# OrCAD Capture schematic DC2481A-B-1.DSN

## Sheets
1 PAGE1: size C; title: HIGH EFFICIENCY, POLY-PHASE, DC/DC STEP-DOWN; rev: 1; company: TM
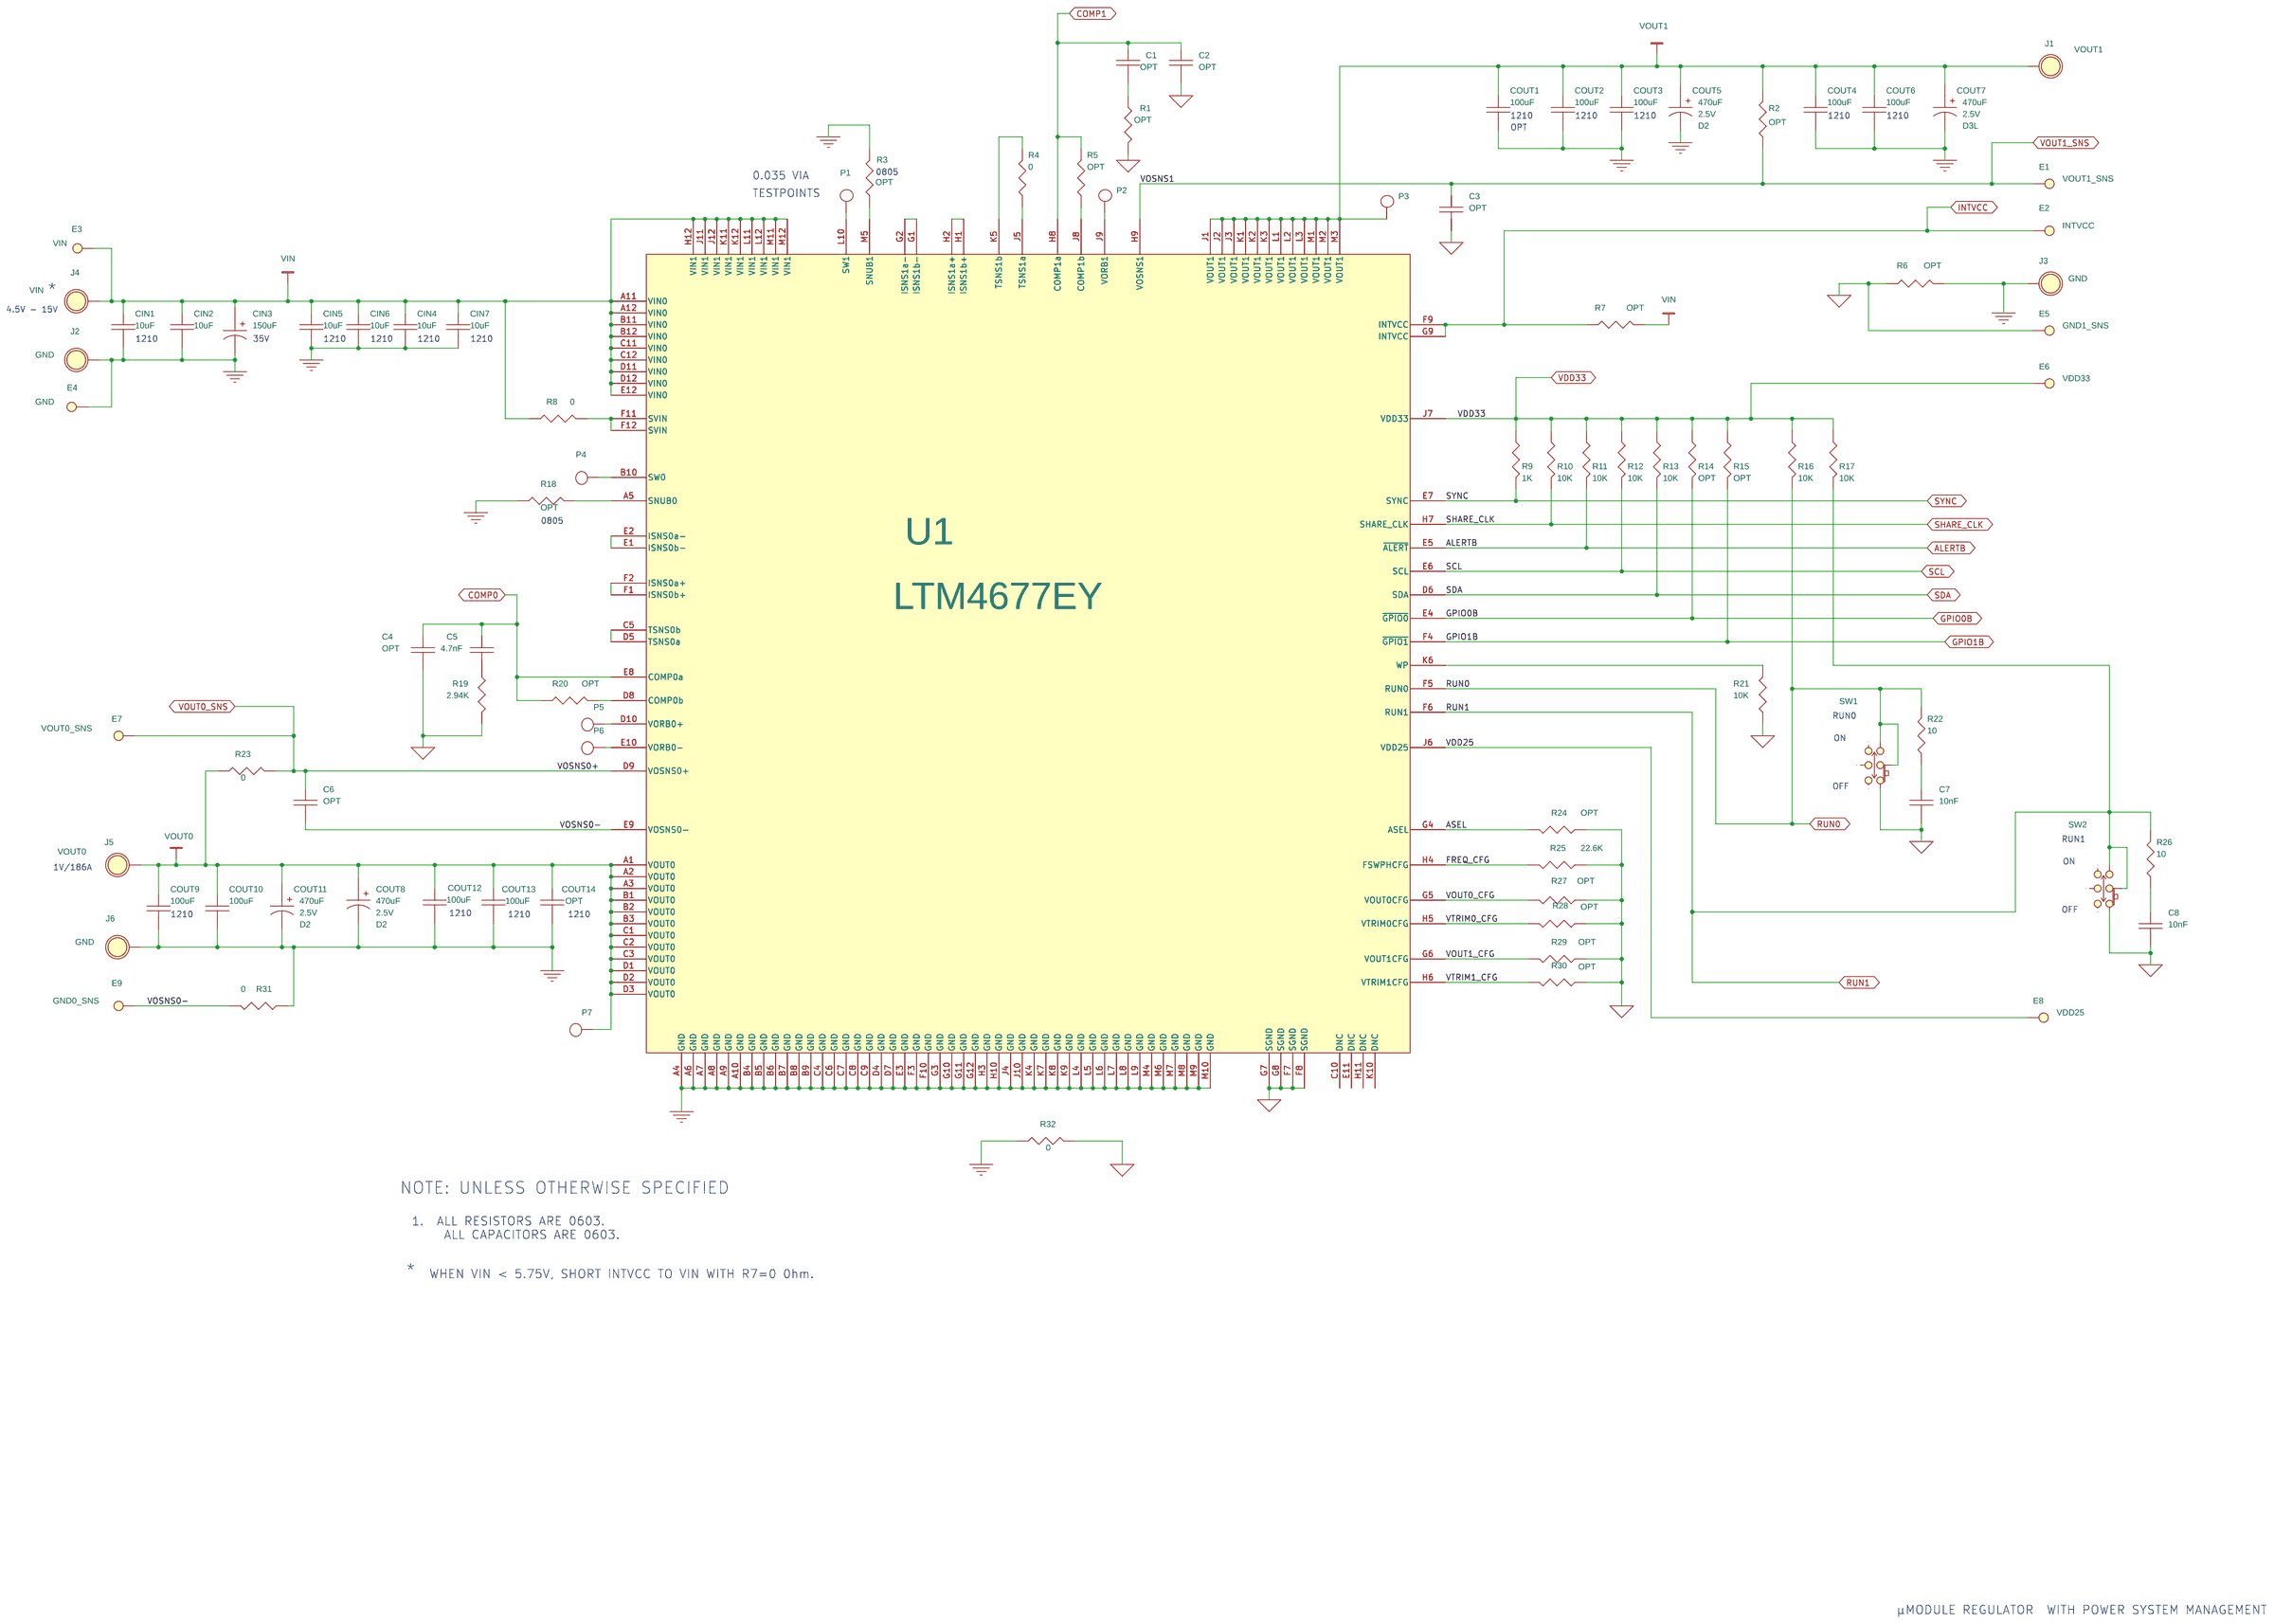
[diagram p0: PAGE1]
2 PAGE2: size Custom
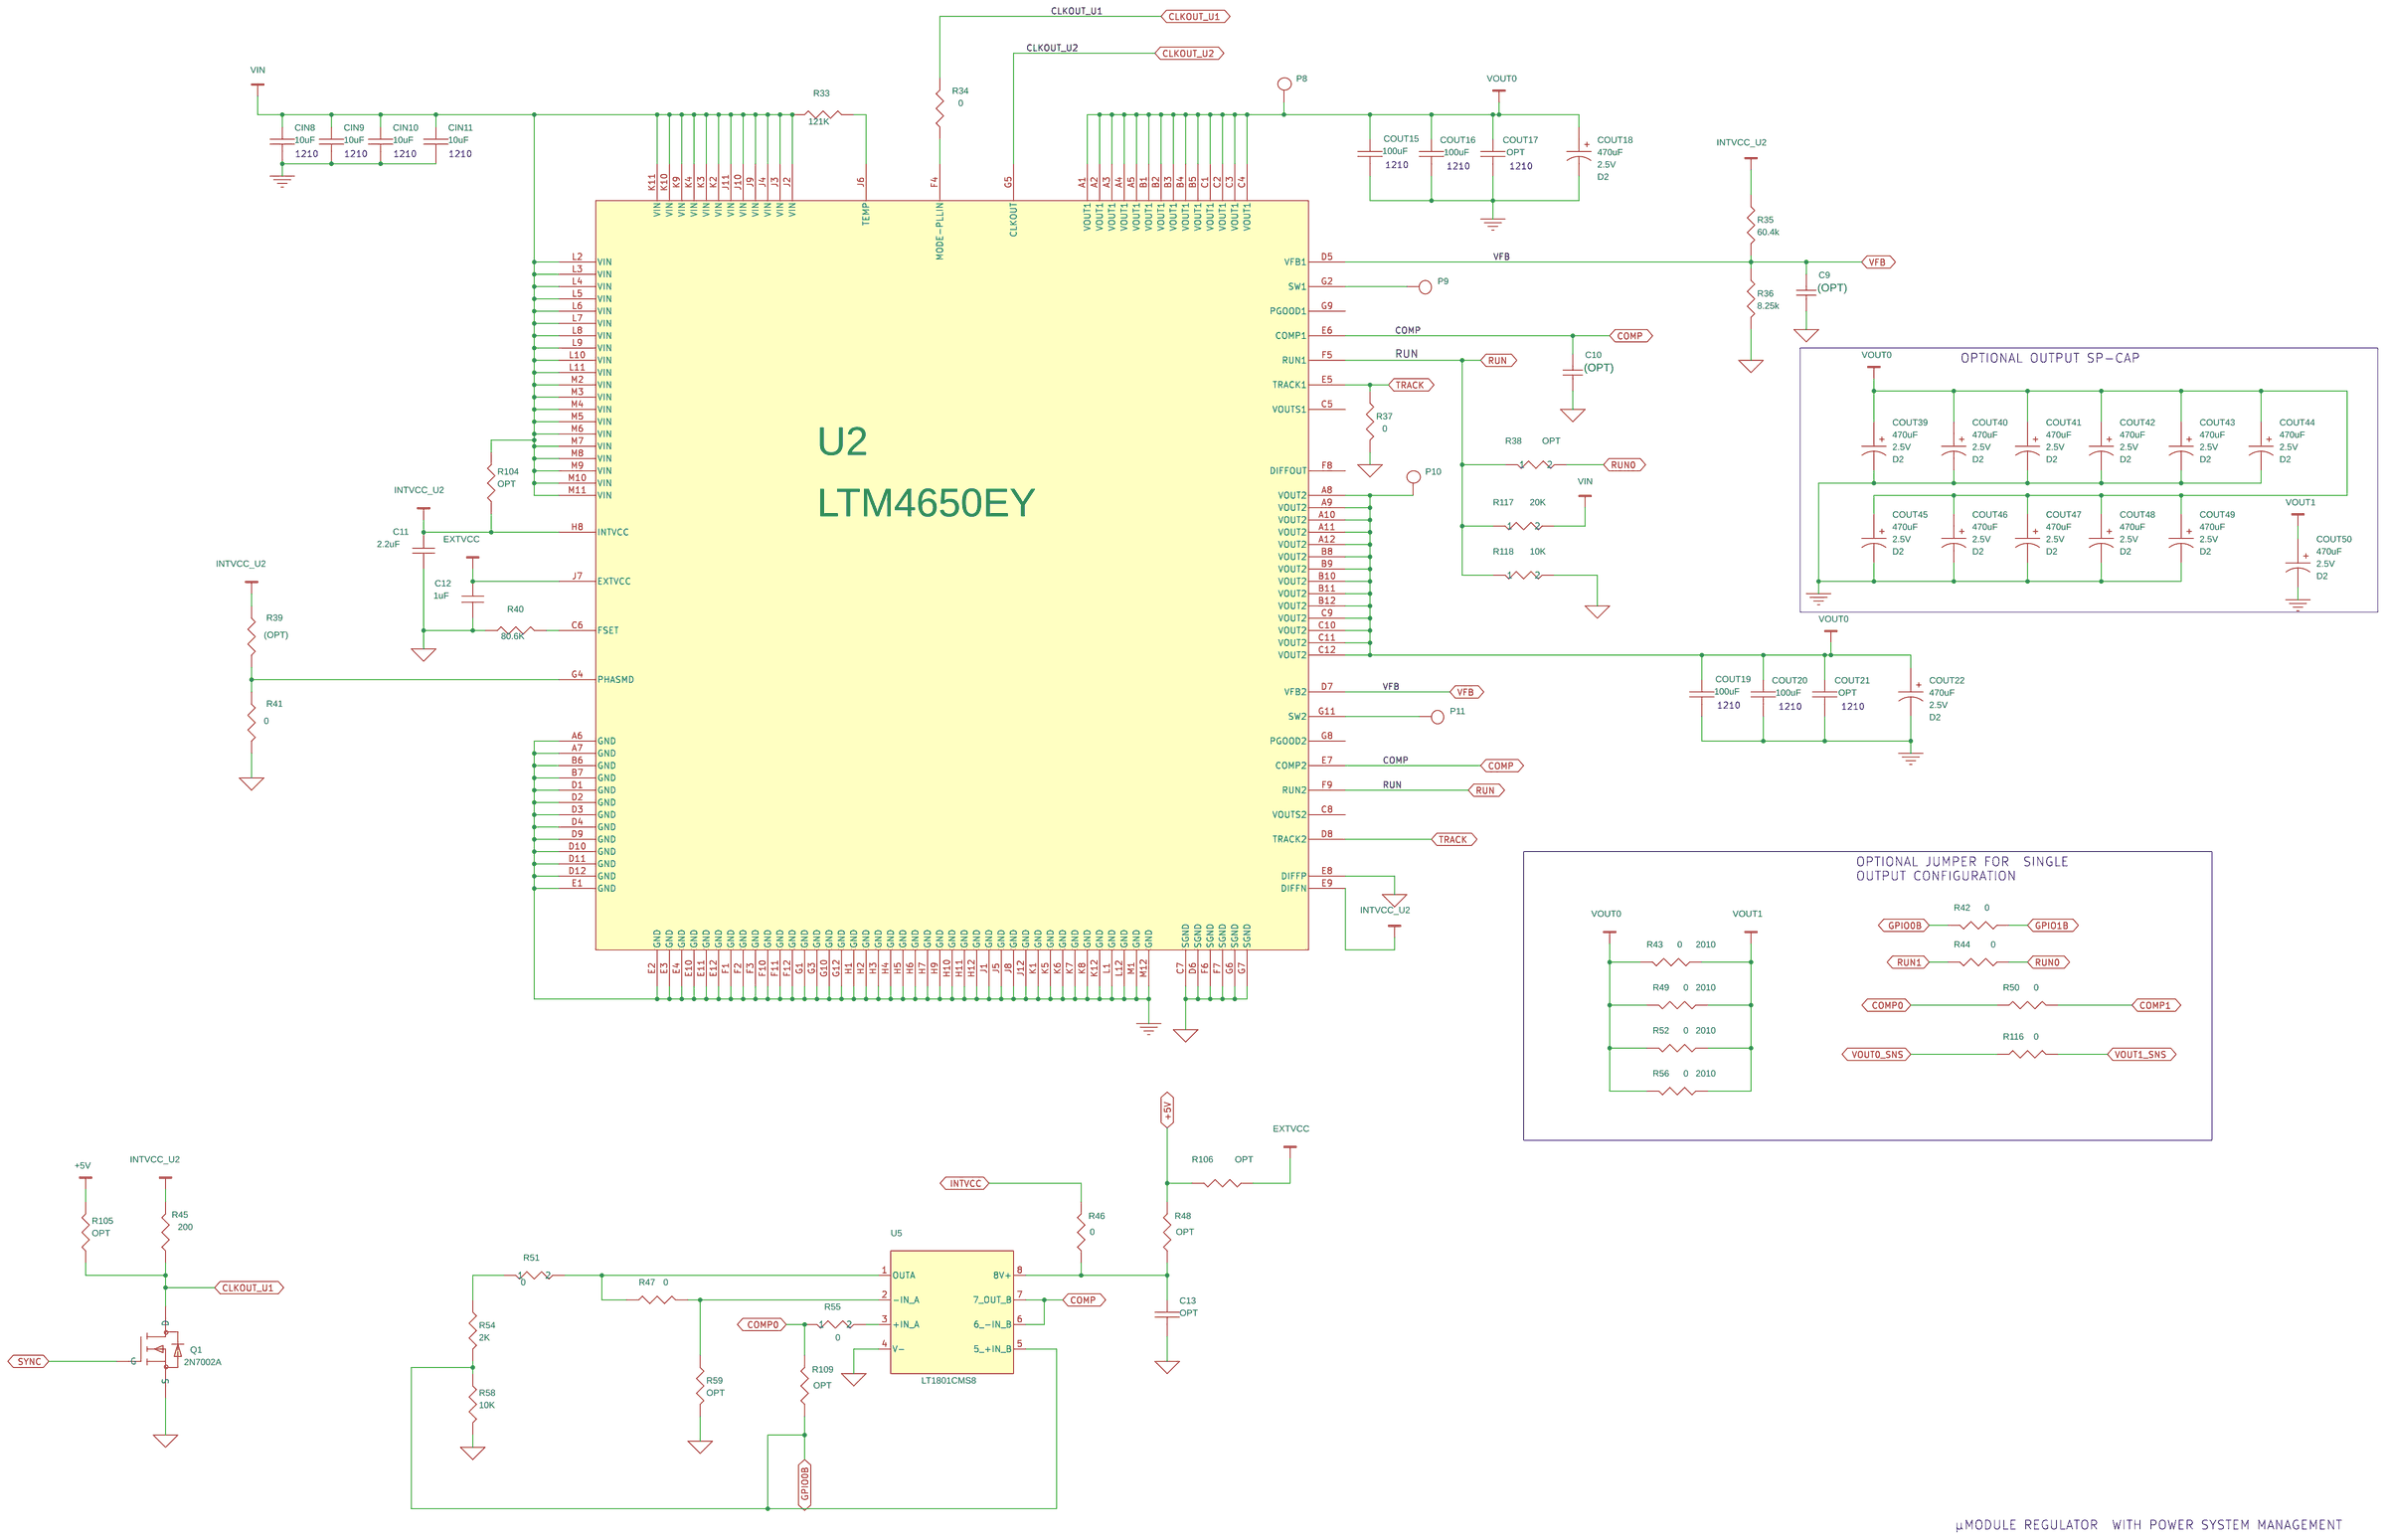
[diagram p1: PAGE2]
3 PAGE3: size Custom
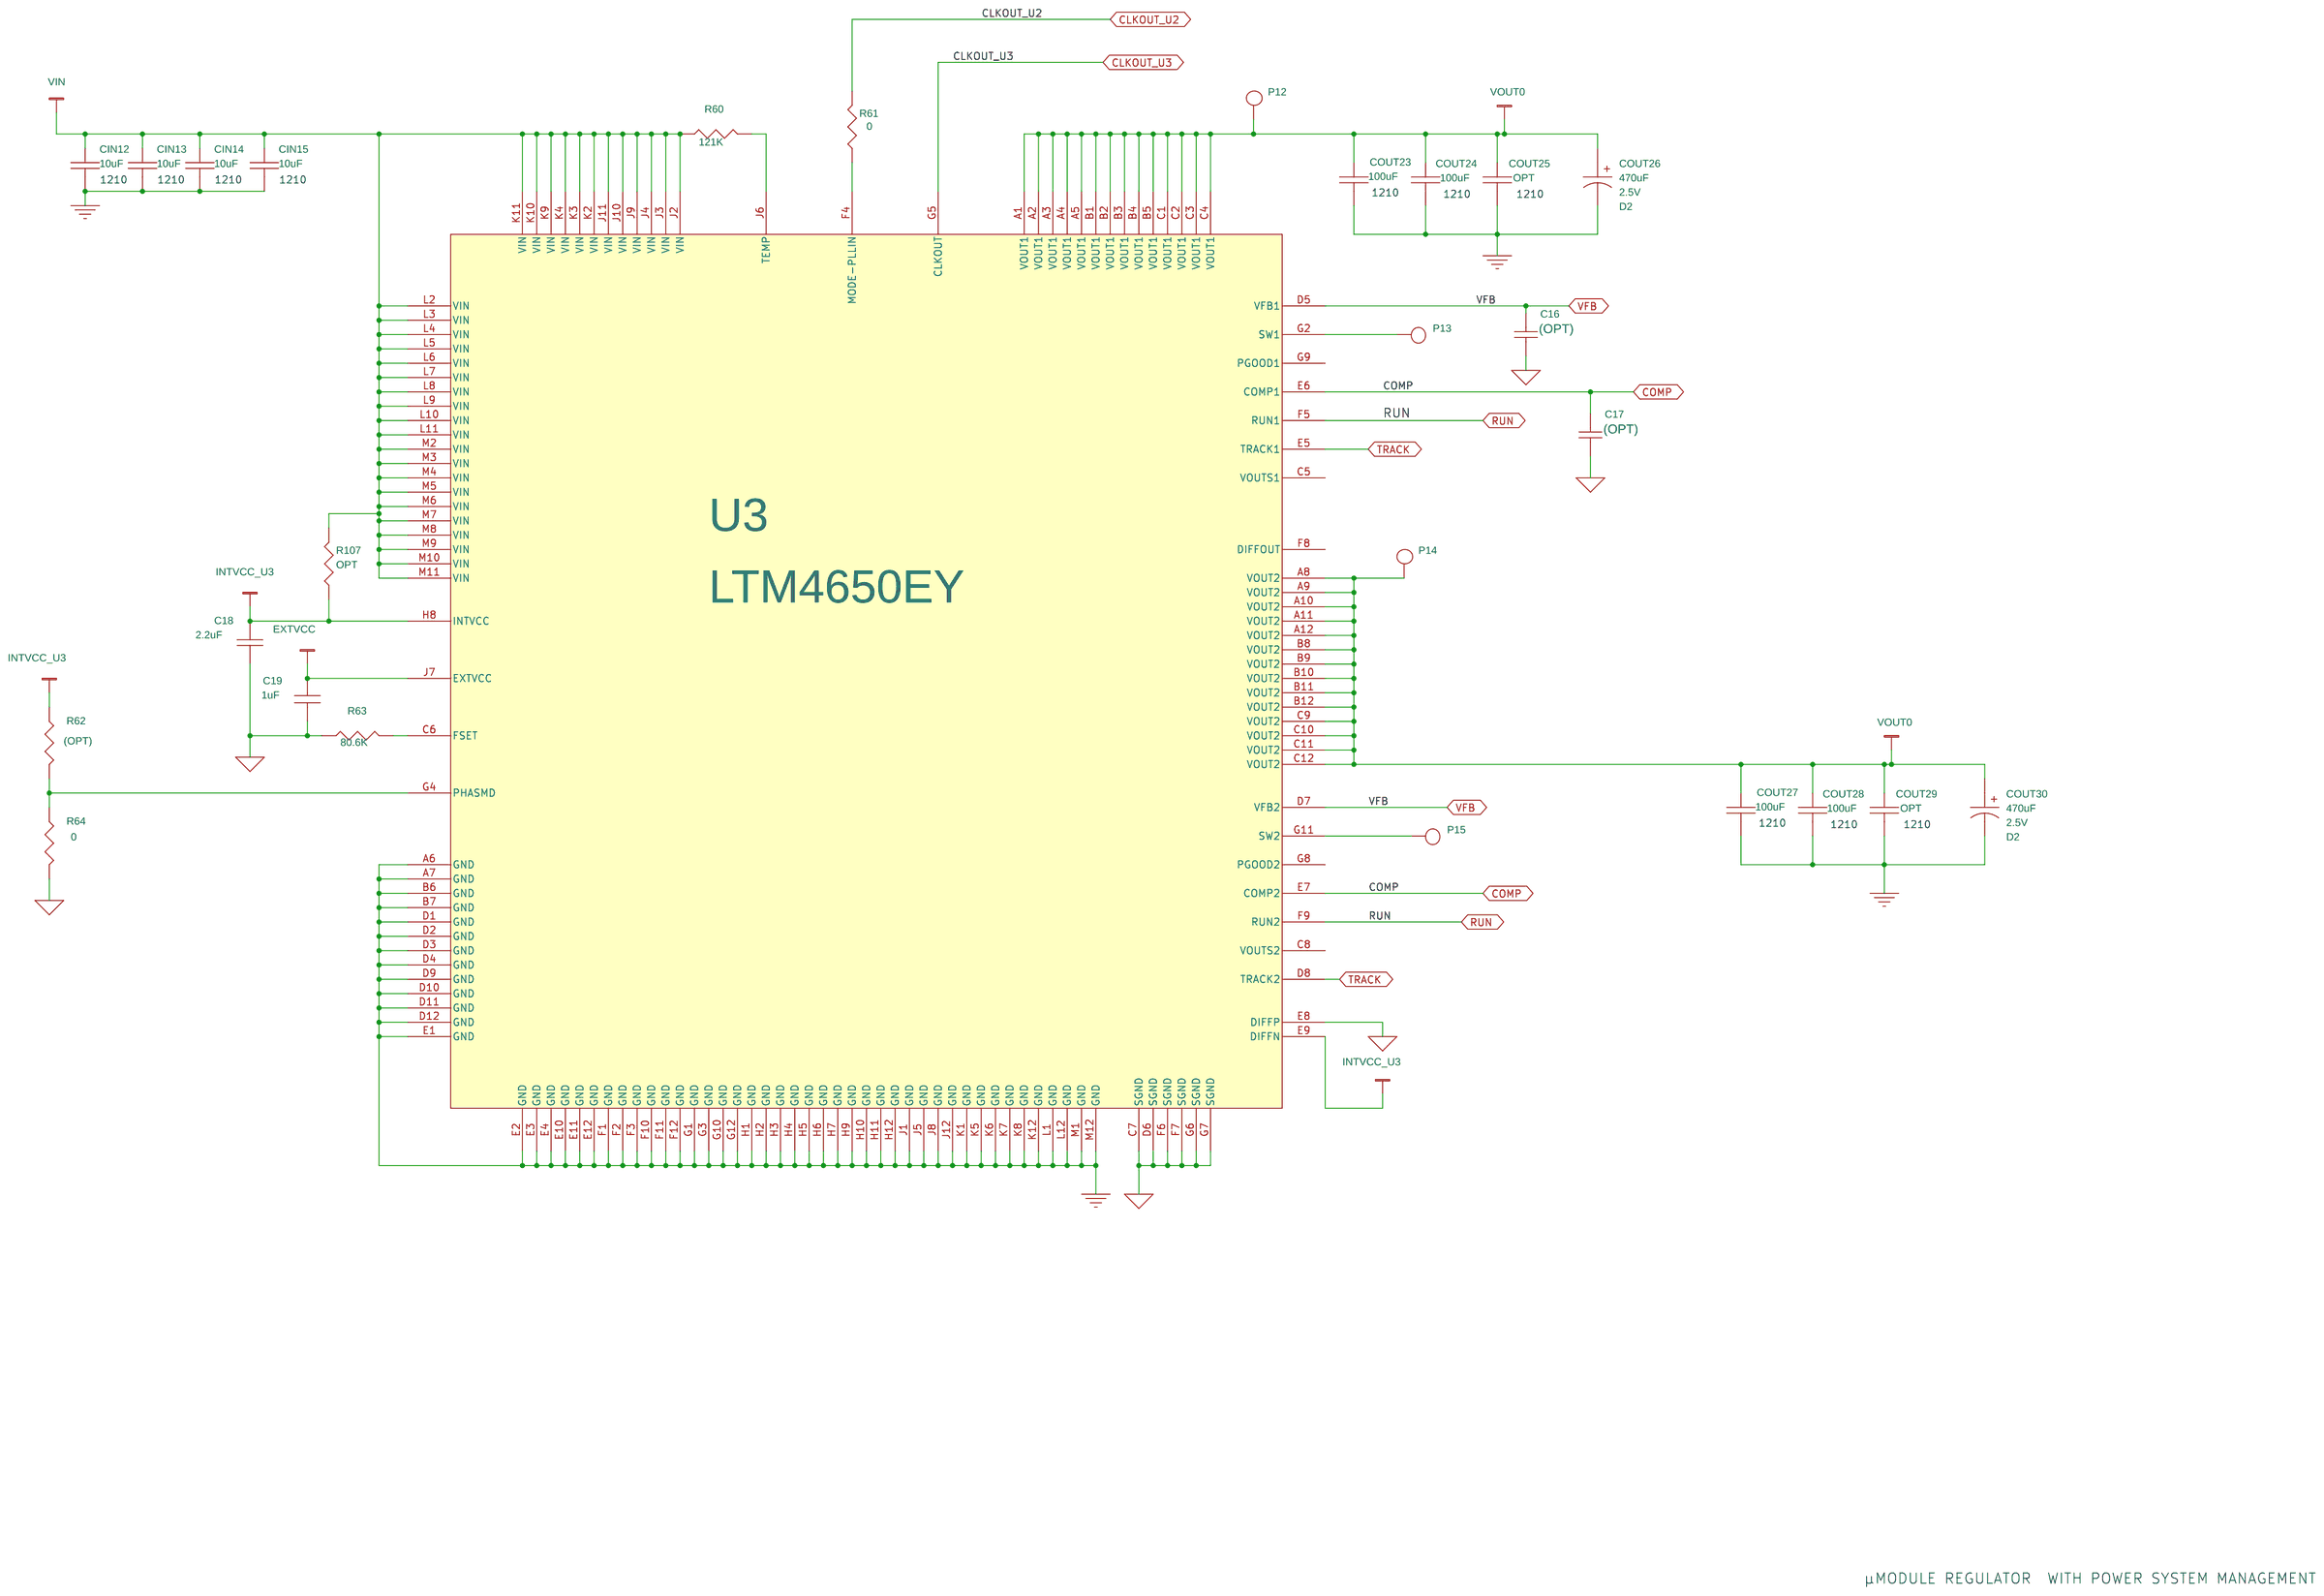
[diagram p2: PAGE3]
4 PAGE4: size Custom
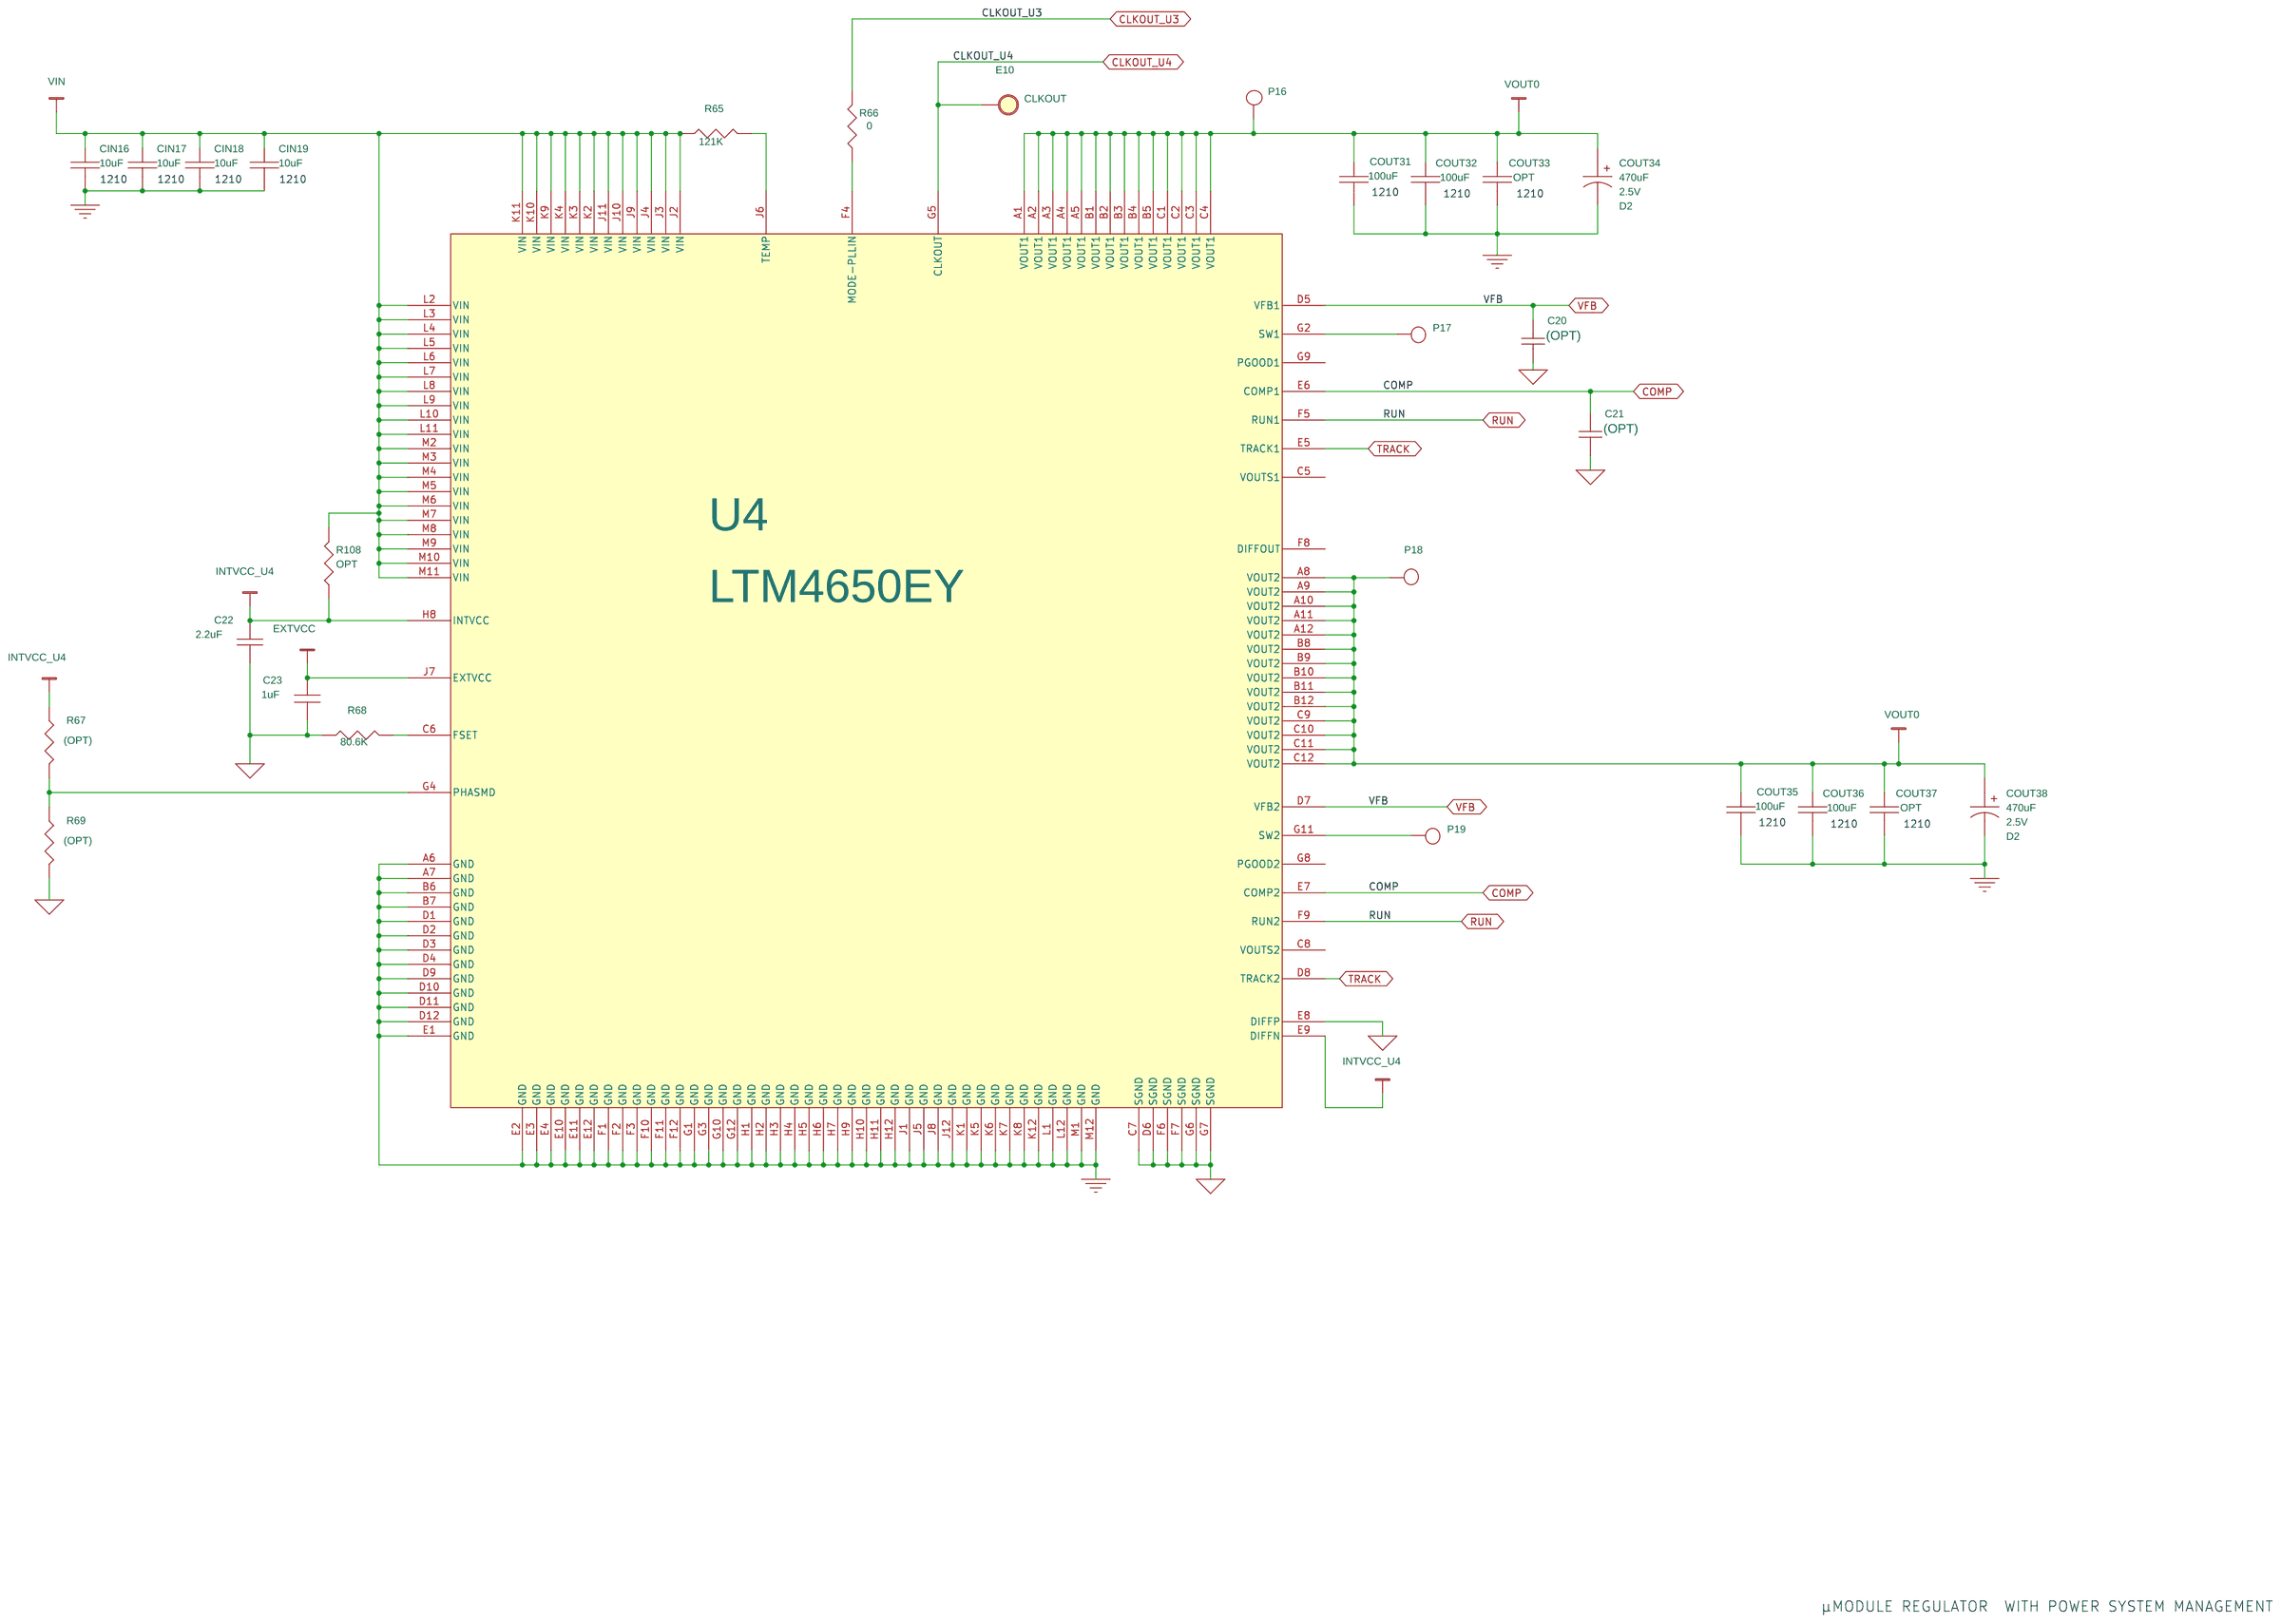
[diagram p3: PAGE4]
5 PAGE5: size Custom
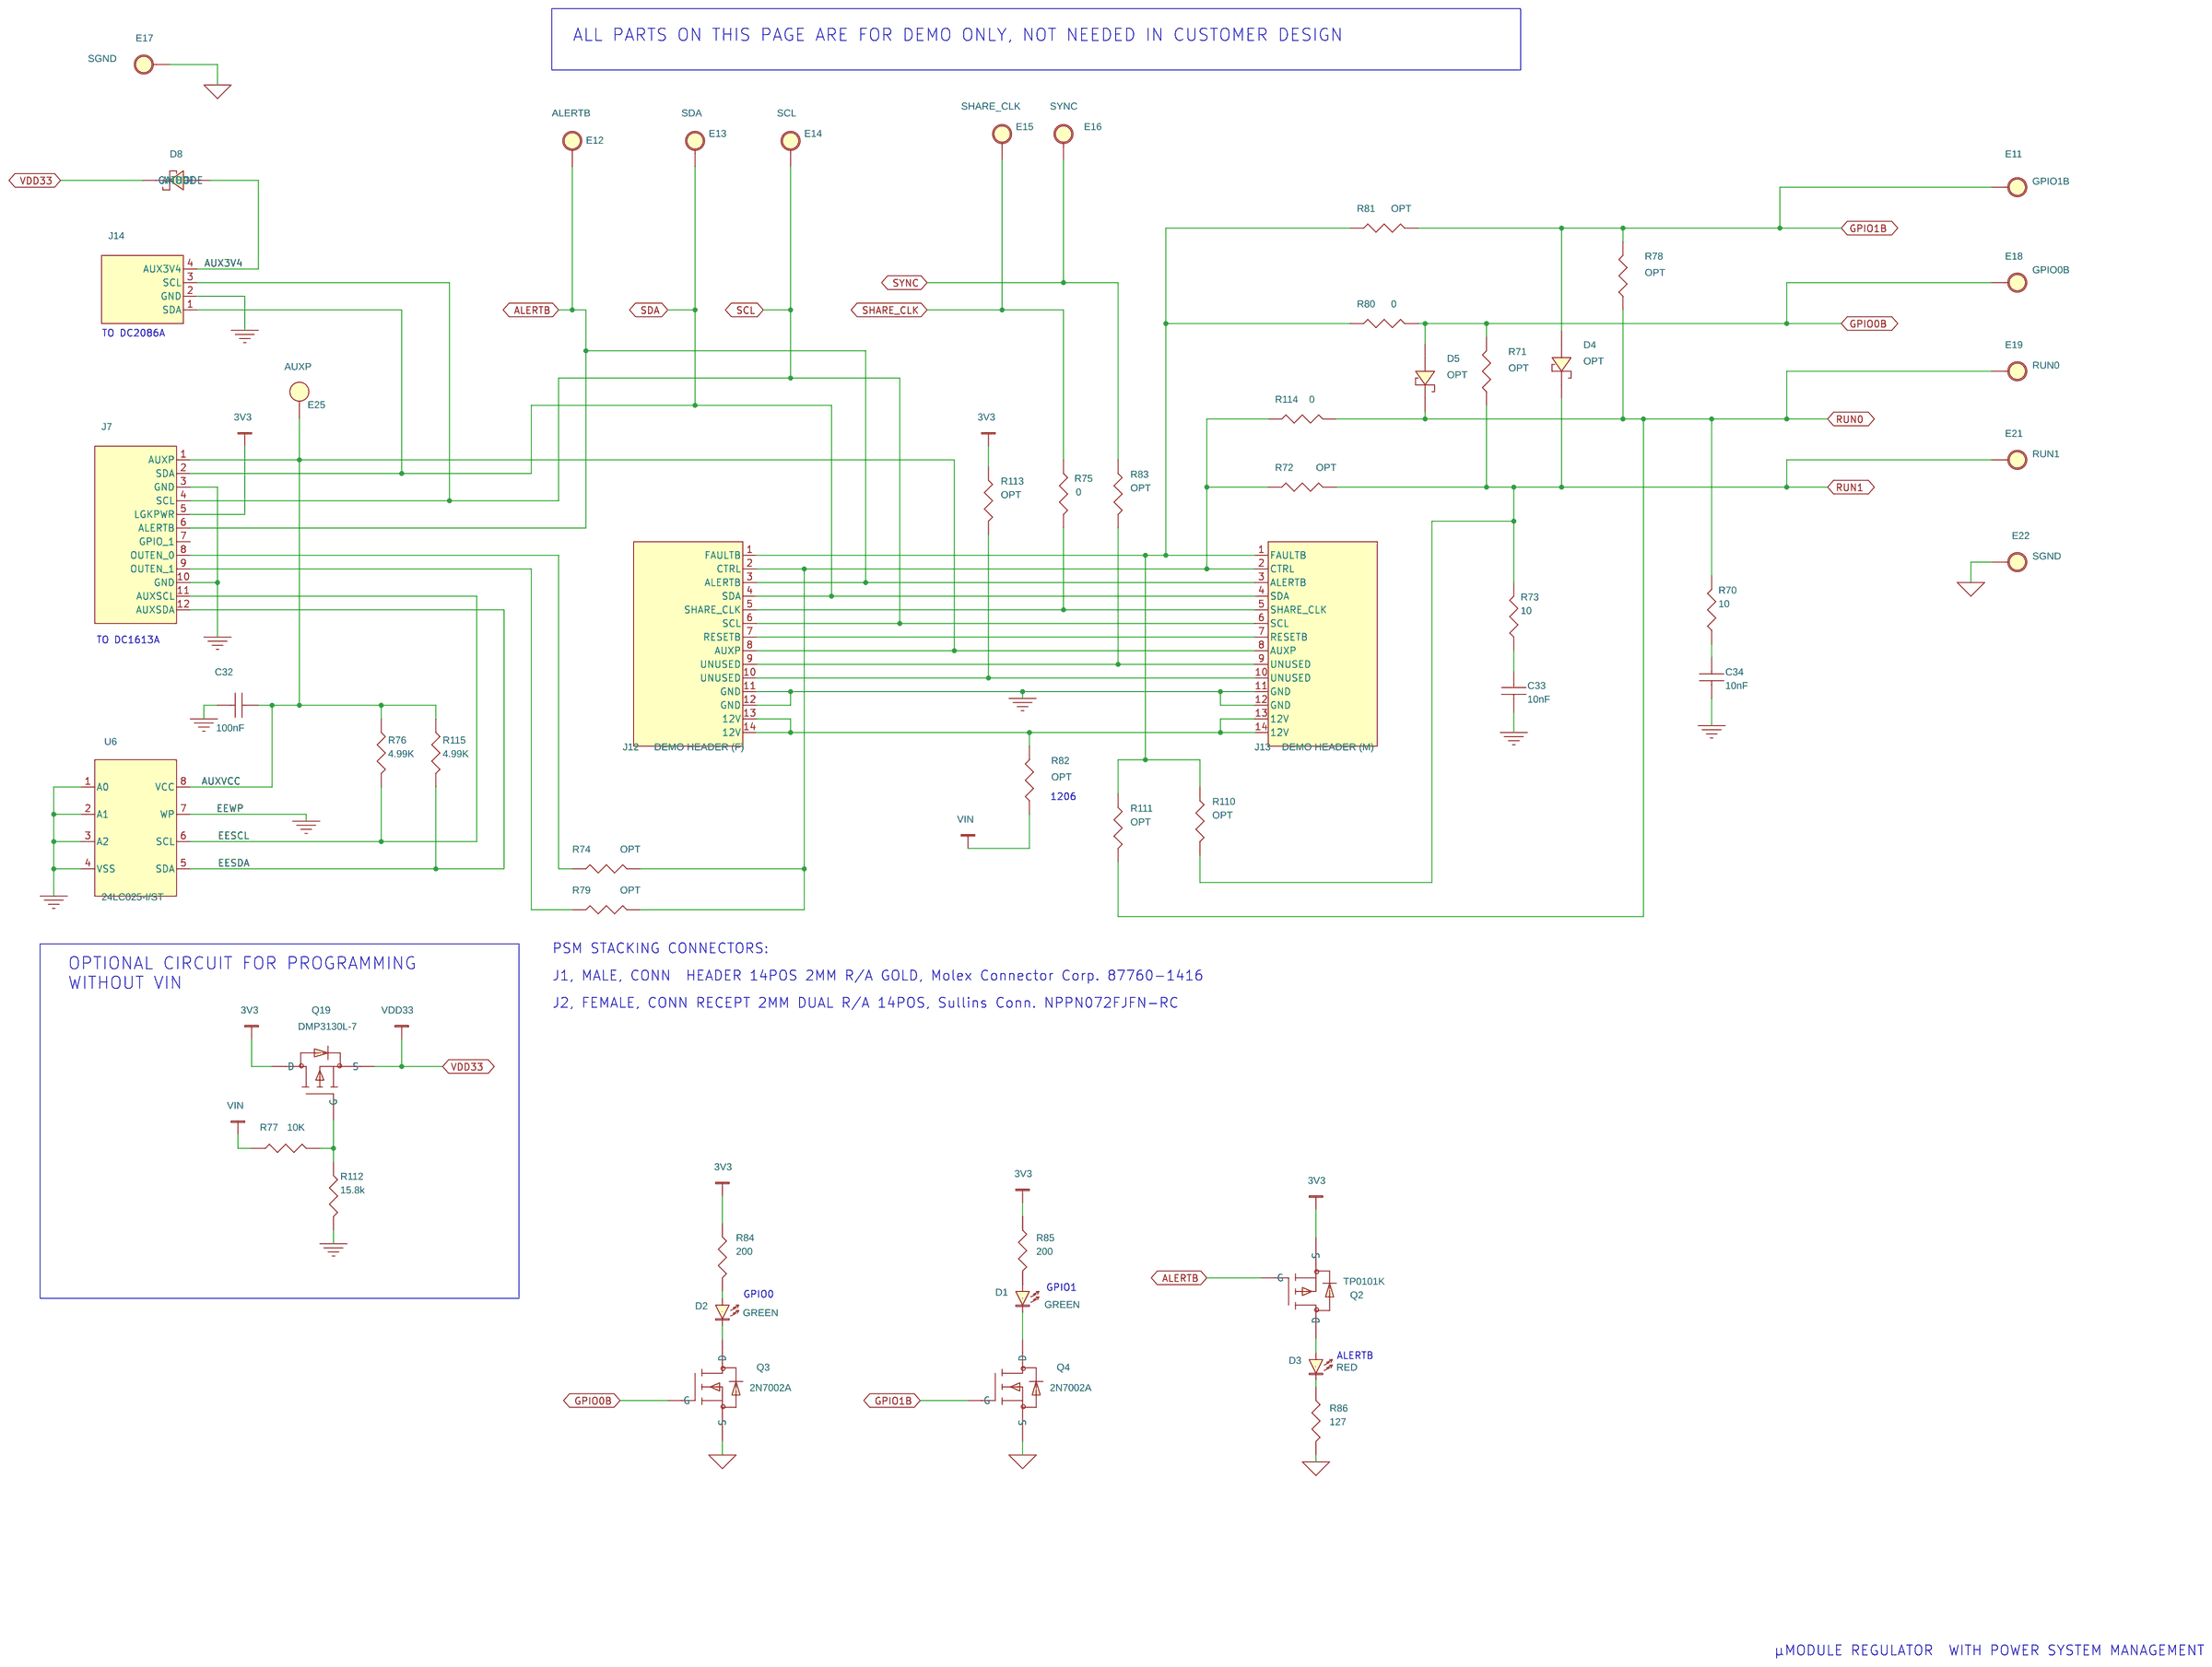
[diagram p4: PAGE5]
6 PAGE6: size B
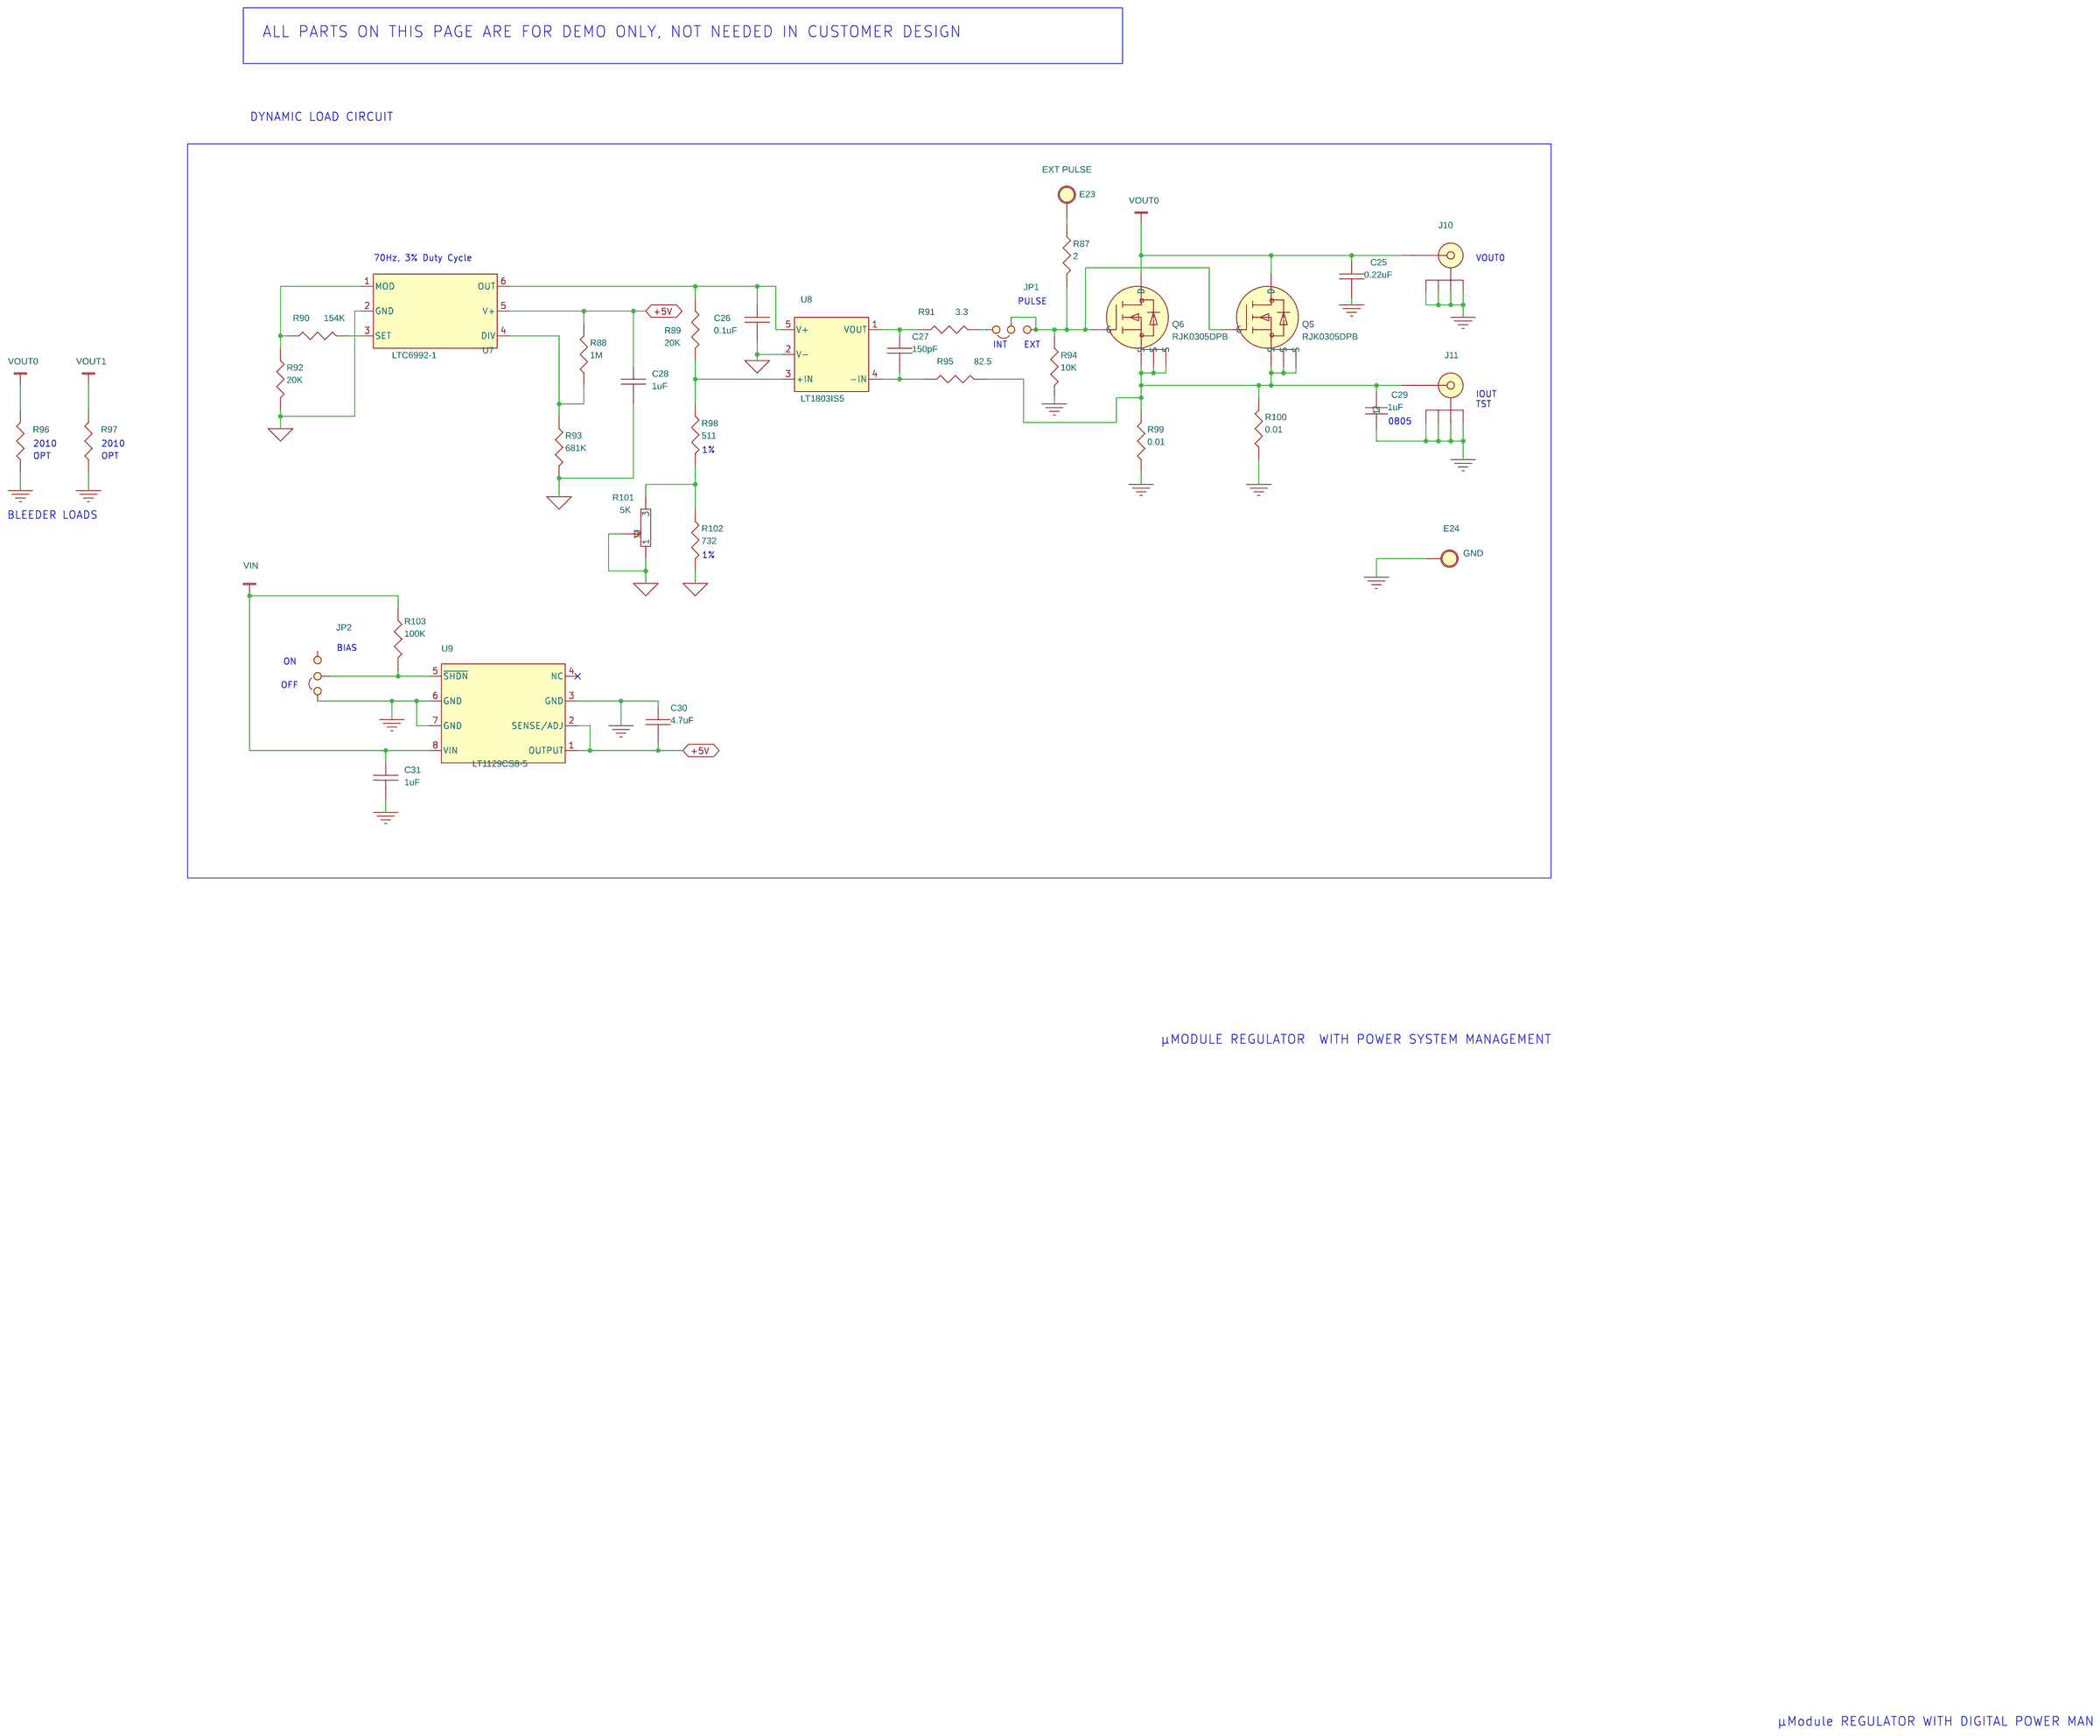
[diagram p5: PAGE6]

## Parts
sheet PAGE1
C1  OPT  [0603]
C2  OPT  [0603]
C3  OPT  [0603]
C4  OPT  [0603]
C5  4.7nF  [0603]
C6  OPT  [0603]
C7  10nF  [0603]
C8  10nF  [0603]
CIN1  10uF  [1210]
CIN2  10uF  [1210]
CIN3  150uF  [SANYO\8X10]
CIN4  10uF  [1210]
CIN5  10uF  [1210]
CIN6  10uF  [1210]
CIN7  10uF  [1210]
COUT1  100uF  [1210]
COUT2  100uF  [1210]
COUT3  100uF  [1210]
COUT4  100uF  [1210]
COUT5  470uF  [D2]
COUT6  100uF  [1210]
COUT7  470uF  [D3L]
COUT8  470uF  [D2]
COUT9  100uF  [1210]
COUT10  100uF  [1210]
COUT11  470uF  [D2]
COUT12  100uF  [1210]
COUT13  100uF  [1210]
COUT14  OPT  [1210]
E1  TURRETS  [TURRETS]
E2  INTVCC  [TURRETS]
E3  TURRETS  [TURRETS]
E4  GND  [TURRETS]
E5  TURRETS  [TURRETS]
E6  VDD33  [TURRETS]
E7  TURRETS  [TURRETS]
E8  VDD25  [TURRETS]
E9  TURRETS  [TURRETS]
J1  BANANA SMALL  [CON\LUG\10]
J2  BANANA SMALL  [CON\LUG\10]
J3  BANANA SMALL  [CON\LUG\10]
J4  BANANA SMALL  [CON\LUG\10]
J5  BANANA SMALL  [CON\LUG\10]
J6  BANANA SMALL  [CON\LUG\10]
P1  TURRETS  [PAD]
P2  TURRETS  [PAD]
P3  TURRETS  [PAD]
P4  TURRETS  [PAD]
P5  TURRETS  [PAD]
P6  TURRETS  [PAD]
P7  TURRETS  [PAD]
R1  OPT  [0603]
R2  OPT  [0603]
R3  OPT  [0805]
R4  0  [0603]
R5  OPT  [0603]
R6  OPT  [0603]
R7  OPT  [0603]
R8  0  [0603]
R9  1K  [0603]
R10  10K  [0603]
R11  10K  [0603]
R12  10K  [0603]
R13  10K  [0603]
R14  OPT  [0603]
R15  OPT  [0603]
R16  10K  [0603]
R17  10K  [0603]
R18  OPT  [0805]
R19  2.94K  [0603]
R20  OPT  [0603]
R21  10K  [0603]
R22  10  [0603]
R23  0  [0603]
R24  OPT  [0603]
R25  22.6K  [0603]
R26  10  [0603]
R27  OPT  [0603]
R28  OPT  [0603]
R29  OPT  [0603]
R30  OPT  [0603]
R31  0  [0603]
R32  0  [0603]
SW1  JP3X1/079\NO\12  [JS202011]
SW2  JP3X1/079\NO\12  [JS202011]
U1  LTM4677EY  [a]
sheet PAGE2
C9  TBD  [0603]
C10  TBD  [0603]
C11  2.2uF  [0603]
C12  1uF  [0603]
C13  OPT  [0603]
CIN8  10uF  [1210]
CIN9  10uF  [1210]
CIN10  10uF  [1210]
CIN11  10uF  [1210]
COUT15  100uF  [1210]
COUT16  100uF  [1210]
COUT17  OPT  [1210]
COUT18  470uF  [D2]
COUT19  100uF  [1210]
COUT20  100uF  [1210]
COUT21  OPT  [1210]
COUT22  470uF  [D2]
COUT39  470uF  [D2]
COUT40  470uF  [D2]
COUT41  470uF  [D2]
COUT42  470uF  [D2]
COUT43  470uF  [D2]
COUT44  470uF  [D2]
COUT45  470uF  [D2]
COUT46  470uF  [D2]
COUT47  470uF  [D2]
COUT48  470uF  [D2]
COUT49  470uF  [D2]
COUT50  470uF  [D2]
P8  TURRETS  [PAD]
P9  TURRETS  [PAD]
P10  TURRETS  [PAD]
P11  TURRETS  [PAD]
Q1  2N7002A  [SOT-23]
R33  121K  [0603]
R34  0  [0603]
R35  60.4k  [0603]
R36  8.25k  [0603]
R37  0  [0603]
R38  OPT  [0603]
R39  TBD  [0603]
R40  80.6K  [0603]
R41  TBD  [0603]
R42  0  [0603]
R43  0  [2010]
R44  0  [0603]
R45  200  [0603]
R46  0  [0603]
R47  0  [0603]
R48  OPT  [0603]
R49  0  [2010]
R50  0  [0603]
R51  0  [0603]
R52  0  [2010]
R54  2K  [0603]
R55  0  [0603]
R56  0  [2010]
R58  10K  [0603]
R59  OPT  [0603]
R104  OPT  [0603]
R105  OPT  [0603]
R106  OPT  [0603]
R109  OPT  [0603]
R116  0  [0603]
R117  20K  [0603]
R118  10K  [0603]
U2  Volt. Reg.  [LTM4620]
U5  LT1801CMS8  [MSOP-8]
sheet PAGE3
C16  TBD  [0603]
C17  TBD  [0603]
C18  2.2uF  [0603]
C19  1uF  [0603]
CIN12  10uF  [1210]
CIN13  10uF  [1210]
CIN14  10uF  [1210]
CIN15  10uF  [1210]
COUT23  100uF  [1210]
COUT24  100uF  [1210]
COUT25  OPT  [1210]
COUT26  470uF  [D2]
COUT27  100uF  [1210]
COUT28  100uF  [1210]
COUT29  OPT  [1210]
COUT30  470uF  [D2]
P12  TURRETS  [PAD]
P13  TURRETS  [PAD]
P14  TURRETS  [PAD]
P15  TURRETS  [PAD]
R60  121K  [0603]
R61  0  [0603]
R62  TBD  [0603]
R63  80.6K  [0603]
R64  TBD  [0603]
R107  OPT  [0603]
U3  Volt. Reg.  [LTM4620]
sheet PAGE4
C20  TBD  [0603]
C21  TBD  [0603]
C22  2.2uF  [0603]
C23  1uF  [0603]
CIN16  10uF  [1210]
CIN17  10uF  [1210]
CIN18  10uF  [1210]
CIN19  10uF  [1210]
COUT31  100uF  [1210]
COUT32  100uF  [1210]
COUT33  OPT  [1210]
COUT34  470uF  [D2]
COUT35  100uF  [1210]
COUT36  100uF  [1210]
COUT37  OPT  [1210]
COUT38  470uF  [D2]
E10  TURRETS  [TURRETS]
P16  TURRETS  [PAD]
P17  TURRETS  [PAD]
P18  TURRETS  [PAD]
P19  TURRETS  [PAD]
R65  121K  [0603]
R66  0  [0603]
R67  TBD  [0603]
R68  80.6K  [0603]
R69  TBD  [0603]
R108  OPT  [0603]
U4  Volt. Reg.  [LTM4620]
sheet PAGE5
C32  100nF  [0603]
C33  10nF  [0603]
C34  10nF  [0603]
D1  GREEN  [led]
D2  GREEN  [led]
D3  RED  [led]
D4  OPT  [SOD323]
D5  OPT  [SOD323]
D8  DIODE SCHOTTKY  [PMEG2005AEL]
E11  TURRETS  [TURRETS]
E12  TURRETS  [TURRETS]
E13  TURRETS  [TURRETS]
E14  TURRETS  [TURRETS]
E15  TURRETS  [TURRETS]
E16  TURRETS  [TURRETS]
E17  SGND  [TURRETS]
E18  TURRETS  [TURRETS]
E19  TURRETS  [TURRETS]
E21  TURRETS  [TURRETS]
E22  SGND  [TURRETS]
E25  AUXP  [TURRETS]
J7  HD2X6-079  [HD2X6-079-MOLEX]
J12  DEMO HEADER (F)  [NPPN072FJFN-RC]
J13  DEMO HEADER (M)  [NPPN072FJFN]
J14  HD2X6-079-PMBUS_0  [DF3A-4P-2DSA]
Q2  TP0101K  [SOT-23]
Q3  2N7002A  [SOT-23]
Q4  2N7002A  [SOT-23]
Q19  DMP3130L-7  [SOT-23]
R70  10  [0603]
R71  OPT  [0603]
R72  OPT  [0603]
R73  10  [0603]
R74  OPT  [0603]
R75  0  [0603]
R76  4.99K  [0603]
R77  10K  [0603]
R78  OPT  [0603]
R79  OPT  [0603]
R80  0  [0603]
R81  OPT  [0603]
R82  OPT  [1206]
R83  OPT  [0603]
R84  200  [0603]
R85  200  [0603]
R86  127  [0603]
R110  OPT  [0603]
R111  OPT  [0603]
R112  15.8k  [0603]
R113  OPT  [0603]
R114  0  [0603]
R115  4.99K  [0603]
U6  24LC025-I/ST  [TSSOP-8_4.4MM]
sheet PAGE6
C25  0.22uF  [0805]
C26  0.1uF  [1206]
C27  150pF  [0603]
C28  1uF  [1206]
C29  1uF  [0805]
C30  4.7uF  [0603]
C31  1uF  [1206]
E23  TURRETS  [TURRETS]
E24  TURRETS  [TURRETS]
J10  XXX  [BNC]
J11  XXX  [BNC]
JP1  JP3X1/079\NO\12  [HD1X3-079]
JP2  JP3X1/079\NO\12  [HD1X3-079]
Q5  RJK0305DPB  [LFPAK]
Q6  RJK0305DPB  [LFPAK]
R87  2  [0603]
R88  1M  [0603]
R89  20K  [0603]
R90  154K  [0603]
R91  3.3  [0603]
R92  20K  [0603]
R93  681K  [0603]
R94  10K  [0603]
R95  82.5  [0603]
R96  OPT  [2512SENSE]
R97  OPT  [2512SENSE]
R98  511  [0603]
R99  0.01  [2010]
R100  0.01  [2010]
R101  5K  [POTENTIOMETER/3386]
R102  732  [0603]
R103  100K  [0603]
U7  LTC6992-1  [S6-TSOT23]
U8  LT1803IS5  [S5-TSOT23]
U9  LT1129CS8-5  [SO8NB]

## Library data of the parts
C1-C6 = CAP0603_1: Component: cap; Manufacturer: TDK; Manufacturer P/N: C1608C0G1H102J; Tolerance: 5%; Type: cer 0603; Vendor: Digikey; Vendor P/N: 445-1293-1-ND; Volts/Amps/Watts: 50V
C7 C8 C27 = CAP0603_2: Component: cap; Manufacturer: TDK; Manufacturer P/N: C1608C0G1H102J; Tolerance: 5%; Type: cer 0603; Vendor: Digikey
CIN1 CIN2 CIN4-CIN19 = CAP1210_1: Component: cap; Manufacturer: Taiyo Yuden; Manufacturer P/N: GMK325BJ106KN-T; Tolerance: 10%; Type: cer 1210; Vendor: Digikey; Vendor P/N: 587-1439-1-ND; Volts/Amps/Watts: 35V
CIN3 = CAPR12X5_0: Component: cap; Manufacturer: SANYO; Tolerance: 20%; Type: OS-CON; Volts/Amps/Watts: 16V
COUT1 = CAP0603_1: Component: cap; Manufacturer: TDK; Manufacturer P/N: C3225X5R0J107M; Tolerance: 20%; Type: cer 1210 X5R; Vendor: Digikey; Vendor P/N: 445-1437-1-ND; Volts/Amps/Watts: 6.3v
COUT2-COUT4 COUT6 COUT9 COUT10 COUT12-COUT17 COUT19-COUT21 COUT23-COUT25 COUT27-COUT29 COUT31-COUT33 COUT35-COUT37 = CAP0603_1: Component: cap; Manufacturer: TDK; Manufacturer P/N: C3225X5R0J107M; Part Type: CAP1210; Tolerance: 20%; Type: cer 1210 X5R; Vendor: Digikey; Vendor P/N: 445-1437-1-ND; Volts/Amps/Watts: 6.3v
COUT5 COUT7 COUT8 COUT11 COUT18 COUT22 COUT26 COUT30 COUT34 COUT38-COUT50 = CAPR12X5_0: Component: cap; Manufacturer: PANASONIC; Manufacturer P/N: EEFGX0E471R; Tolerance: 10%; Type: SP; Volts/Amps/Watts: 2.5V
E1 = TURRETS_1: Component: tp; Label: VOUT1_SNS; Vendor: Digikey; Vendor P/N: 1593-2K-ND
E2 E6 E8 = TURRETS_1: Component: tp; Label: GND; Manufacturer: Keystone; Manufacturer P/N: 1593-2; Vendor: Digikey; Vendor P/N: 1593-2K-ND
E3 = TURRETS_1: Component: tp; Label: VIN; Manufacturer: Keystone; Manufacturer P/N: 1593-2; Vendor: Digikey; Vendor P/N: 1593-2K-ND
E4 = TURRETS_1: Component: tp; Manufacturer: Keystone; Manufacturer P/N: 1593-2; Vendor: Digikey; Vendor P/N: 1593-2K-ND
E5 = TURRETS_1: Component: tp; Label: GND1_SNS; Vendor: Digikey; Vendor P/N: 1593-2K-ND
E7 = TURRETS_1: Component: tp; Label: VOUT0_SNS; Vendor: Digikey; Vendor P/N: 1593-2K-ND
E9 = TURRETS_1: Component: tp; Label: GND0_SNS; Vendor: Digikey; Vendor P/N: 1593-2K-ND
J1 = BANANA_SMALL_0: Component: conn; Label: VOUT1
J2 J3 J6 = BANANA_SMALL_0: Component: conn; Label: GND
J4 = BANANA_SMALL_0: Component: conn; Label: VIN
J5 = BANANA_SMALL_0: Component: conn; Label: VOUT0
P1-P19 = PAD_2: Component: tp; Label: <Label>; Vendor: Digikey; Vendor P/N: 1593-2K-ND
R1 R19 R35-R37 R45-R48 R54 R58 R59 R109 = RES0603_9: Component: res; Label: <label>; Manufacturer: Panasonic; Manufacturer P/N: ERJ-3EKF5901V; Tolerance: 1%; Vendor: Digikey; Vendor P/N: P5.90KHCT-ND; Volts/Amps/Watts: 0.1W
R2 = RES0603_9: Label: 0; Manufacturer: Rohm; Manufacturer P/N: RHM0.0GCT-ND; Tolerance: 5%; Vendor: Digikey; Vendor P/N: RHM0.0GCT-ND; Volts/Amps/Watts: 0.1W
R3 R18 = RES0603_9
R4 R5 R20 = RES0603_9: Manufacturer: Rohm; Manufacturer P/N: RHM0.0GCT-ND; Tolerance: 5%; Vendor: Digikey; Vendor P/N: RHM0.0GCT-ND; Volts/Amps/Watts: 0.1W
R6 R8 R32 R50 R116 = RES0603_3
R7 = RES0603_9: Label: OPT 0; Manufacturer: Rohm; Manufacturer P/N: RHM0.0GCT-ND; Vendor: Digikey
R9-R17 R21 R28 R29 = RES0603_9: Manufacturer: ROHM; Manufacturer P/N: MCR03EZPFX1002; Vendor: Digikey; Vendor P/N: RHM10.0KHCT-ND; Volts/Amps/Watts: 0.1W
R22 R26 = RES0603_1: Manufacturer: Rohm; Manufacturer P/N: RHM0.0GCT-ND; Tolerance: 5%; Vendor: Digikey; Vendor P/N: RHM0.0GCT-ND; Volts/Amps/Watts: 0.1W
R23 = RES0603_9: Manufacturer: Rohm; Manufacturer P/N: MCR03EZPFX1000; Vendor: Digikey; Vendor P/N: RHM100HCT-ND; Volts/Amps/Watts: 0.1W
R24 R25 = RES0603_9: Manufacturer: Panasonic; Manufacturer P/N: ERJ-3EKF2002V; Vendor: Digikey; Vendor P/N: P20.0KHCT-ND; Volts/Amps/Watts: 0.1W
R27 = RES0603_9: Manufacturer: Panasonic; Manufacturer P/N: ERJ-3EKF1000V; Vendor: Digikey; Vendor P/N: P100HCT-ND; Volts/Amps/Watts: 0.1W
R30 = RES0603_9: Manufacturer: Panasonic; Manufacturer P/N: ERJ-3EKF1021V; Vendor: Digikey; Vendor P/N: P1.02KHCT-ND; Volts/Amps/Watts: 0.1W
R31 = RES0603_9: Manufacturer: Yageo; Manufacturer P/N: RC0603JR-070RL; Tolerance: 5%; Vendor: Digikey; Vendor P/N: 311-0.0GRCT-ND; Volts/Amps/Watts: 0.1W
SW1 SW2 = JP3X1_079_NO_12_3
U1 = LTC3880-M0001_20: Component: IC; Manufacturer: LTC; Manufacturer P/N: LTC3880_M0001; Vendor: LTC; Vendor P/N: LTC3880_M0001
C9 C10 C16 C17 C20 C21 = CAP0603: 6th Part Field: (OPT)
C11 C18 C22 = LMK107BJ225MA
C12 C19 C23 = LMK107BJ105KA
C13 = CAP_3: Manufacturer: Taiyo Yuden; Manufacturer P/N: EMK107B7105KA-T; Type: cer 0603 X7R; Vendor: Digikey; Vendor P/N: 587-1241-1-ND; Volts/Amps/Watts: 16V
Q1 Q3 = TRANSISTOR_0: XSTR, N-CHANNEL DMOS FET
R33 R40 R60 R63 R65 R68 R104-R108 = CRCW0603121KFKEA
R34 R61 R66 = CRCW06030000Z0EA
R38 = R_2: RES, 0603 OPTION; Part Number: OPTION
R39 R62 R67 R69 = RES0603: 6th Part Field: (OPT)
R41 R64 = RES0603: 6th Part Field: 0
R42-R44 R49 R52 R56 R84-R86 = RES0603_9: Label: OPT 0; Manufacturer: Rohm; Manufacturer P/N: RHM0.0GCT-ND; Tolerance: 5%; Vendor: Digikey; Vendor P/N: RHM0.0GCT-ND; Volts/Amps/Watts: 0.1W
R51 = R: RES, 0603 OPTION; Part Number: OPTION
R55 = R_4: RES, 0603 OPTION; Part Number: OPTION
R117 = R_3: RES, 0603 OPTION; Part Number: OPTION
R118 = R_1: RES, 0603 OPTION; Part Number: OPTION
U2-U4 = LTM4620EV_0: 5th Part Field: LTM4650EY
U5 = LTC6244HMS8
E10 = TURRETS_2: Component: tp; Label: CLKOUT; Manufacturer: Keystone; Manufacturer P/N: 1593-2; Vendor: Digikey; Vendor P/N: 1593-2K-ND
C32 = CAP_NP: CAP, 0603 100nF 20% 16V X7R; Part Number: AVX 0603YC104MAT2A
C33 C34 = CAP_NP: CAP, 0603 10nF 10% 25V X7R; Part Number: AVX 06033C103KAT2A
D1 D2 = DIODE-LED_3: Manufacturer: PANASONIC; Manufacturer P/N: LN1371SGTRP
D3 = DIODE-LED_3: Label: GREEN; Manufacturer: PANASONIC
D4 D5 = DIODE_SCHOTTKY_9: DIODE, SCHOTTKY 30V, 100mA; Part Number: CENTRAL SEMI CMDSH-3-TR
D8 = DIODE_SCHOTTKY_0
E11 = TURRETS_2: Component: tp; Label: GPIO1B; Manufacturer: Keystone; Manufacturer P/N: 1593-2; Vendor: Digikey; Vendor P/N: 1593-2K-ND
E12 = TURRETS_2: Component: tp; Label: ALERTB; Manufacturer: Keystone; Manufacturer P/N: 1593-2; Vendor: Digikey; Vendor P/N: 1593-2K-ND
E13 = TURRETS_2: Component: tp; Label: SDA; Manufacturer: Keystone; Manufacturer P/N: 1593-2; Vendor: Digikey; Vendor P/N: 1593-2K-ND
E14 = TURRETS_2: Component: tp; Label: SCL; Manufacturer: Keystone; Manufacturer P/N: 1593-2; Vendor: Digikey; Vendor P/N: 1593-2K-ND
E15 = TURRETS_2: Component: tp; Label: SHARE_CLK; Manufacturer: Keystone; Manufacturer P/N: 1593-2; Vendor: Digikey; Vendor P/N: 1593-2K-ND
E16 = TURRETS_2: Component: tp; Label: SYNC; Manufacturer: Keystone; Manufacturer P/N: 1593-2; Vendor: Digikey; Vendor P/N: 1593-2K-ND
E17 E22 = TURRETS_2: Component: tp; Label: GND; Manufacturer: Keystone; Manufacturer P/N: 1593-2; Vendor: Digikey; Vendor P/N: 1593-2K-ND
E18 = TURRETS_2: Component: tp; Label: GPIO0B; Manufacturer: Keystone; Manufacturer P/N: 1593-2; Vendor: Digikey; Vendor P/N: 1593-2K-ND
E19 = TURRETS_2: Component: tp; Label: RUN0; Manufacturer: Keystone; Manufacturer P/N: 1593-2; Vendor: Digikey; Vendor P/N: 1593-2K-ND
E21 = TURRETS_2: Component: tp; Label: RUN1; Manufacturer: Keystone; Manufacturer P/N: 1593-2; Vendor: Digikey; Vendor P/N: 1593-2K-ND
E25 = E_0: TURRET; Part Number: MILL MAX 2501-2-00-80-00-00-07-0
J7 = HD2X6-079-PMBUS_2: HEADER, 12PIN 2mm STR DL; Label: DC1427A HEADER; Manufacturer: MOLEX; Manufacturer P/N: 87831-1220; Part Number: FCI 98414-G06-12ULF; Type: header 12POS 2MM VERT; Vendor: Digikey; Vendor P/N: WM18561-ND
J12 = PMBUS_HEADER20_3: HEADER, 20PIN DUAL ROW R/A; Component: con; Manufacturer: Mill Max; Manufacturer P/N: 802-40-020-20-0001; Part Number: MILL MAX 802-40-020-20-0001; Type: header RA 20 dual row; Vendor: LTC; Vendor P/N: 802-40-020-20-001
J13 = PMBUS_CONNECTOR20_3: CONN, SOCKET 20PIN  DUAL ROW R/A; Component: con; Manufacturer: Mill Max; Manufacturer P/N: 803-93-020-20-001; Part Number: MILL MAX 803-93-020-20-001; Type: conn  RA 20 dual row; Vendor: LTC; Vendor P/N: 803-93-020-20-001
J14 = HD2X6-079-PMBUS_4: HEADER, 4PIN 2mm STR DL; Manufacturer: Hirose; Type: header 4POS 2MM VERT
Q2 = P-MOSFET: XSTR, N-CHANNEL DMOS FET
Q4 = TRANSISTOR_1: XSTR, N-CHANNEL DMOS FET
Q19 = P-MOSFET: XSTR, N-CHANNEL DMOS FET; Part Number: VISHAY TP0101K-T1-E3
R70 R73 = RES0603_1: RES, 0603 10 OHMS 5% 1/10W; Manufacturer: Rohm; Manufacturer P/N: RHM0.0GCT-ND; Part Number: VISHAY CRCW060310R0JNEA; Tolerance: 5%; Vendor: Digikey; Vendor P/N: RHM0.0GCT-ND; Volts/Amps/Watts: 0.1W
R71 R78 R79 R83 R110 R111 R113 = RES0603_0: RES, 0603 OPTION; Label: OPT 0; Manufacturer: Rohm; Manufacturer P/N: RHM0.0GCT-ND; Part Number: OPTION; Tolerance: 5%; Vendor: Digikey; Vendor P/N: RHM0.0GCT-ND; Volts/Amps/Watts: 0.1W
R72 R80 R81 R114 = RES0603_0: RES, 0603 0 OHMS JUMPER; Label: OPT 0; Manufacturer: Rohm; Manufacturer P/N: RHM0.0GCT-ND; Part Number: VISHAY CRCW06030000Z0EA; Tolerance: 5%; Vendor: Digikey; Vendor P/N: RHM0.0GCT-ND; Volts/Amps/Watts: 0.1W
R74 R82 = RES0603_3: RES, 0603 OPTION; Label: OPT 0; Manufacturer: Rohm; Manufacturer P/N: RHM0.0GCT-ND; Part Number: OPTION; Tolerance: 5%; Vendor: Digikey; Vendor P/N: RHM0.0GCT-ND; Volts/Amps/Watts: 0.1W
R75 = RES0603_0: RES, 0603 0 OHMS JUMPER; Manufacturer: Rohm; Manufacturer P/N: RHM0.0GCT-ND; Part Number: VISHAY CRCW06030000Z0EA; Tolerance: 5%; Vendor: Digikey; Vendor P/N: RHM0.0GCT-ND; Volts/Amps/Watts: 0.1W
R76 R115 = RES0603_0: RES, 0603 4.99K OHMS 1% 1/10W; Manufacturer: ROHM; Manufacturer P/N: MCR03EZPFX4991; Part Number: VISHAY CRCW06034K99FKEA; Vendor: Digikey; Vendor P/N: RHM4.99KHCT-ND; Volts/Amps/Watts: 0.1w
R77 = RES0603_11: RES, 0603 10K OHMS 5% 1/10W; Part Number: VISHAY CRCW060310K0JNEA
R112 = RES0603_11: RES, 0603 15.8K OHMS 1% 1/10W; Part Number: VISHAY CRCW060315K8FKEA
U6 = 24LC025-I_SN: IC, 24LC05-I/ST; Part Number: MICROCHIP 24LC025-I/ST
C25 = CAP1206_1: Manufacturer: Kemet; Manufacturer P/N: C1206C106K8RACTU; Tolerance: 10%; Type: cer 1206 X7R; Vendor: Digikey; Vendor P/N: 399-4937-1-ND; Volts/Amps/Watts: 10V
C26 C28 C31 = CAP1206_1: Manufacturer: AVX; Manufacturer P/N: 12063C105KAT2A; Tolerance: 10%; Type: cer 1206 X7R; Vendor: Digikey; Vendor P/N: 478-1567-1-ND; Volts/Amps/Watts: 25V
C29 = CAP_NP_1: CAP, 0603 1.5nF 10% 50V X7R; Part Number: AVX 06033C152KAT
C30 = CAP1206_1: Manufacturer: AVX; Tolerance: 10%; Type: cer 1206 X7R; Vendor: Digikey; Vendor P/N: 478-1567-1-ND; Volts/Amps/Watts: 25V
E23 = TURRETS_2: Label: EXT PULSE; Manufacturer: Keystone; Manufacturer P/N: 1593-2; Vendor: Digikey; Vendor P/N: 1593-2K-ND
E24 = TURRETS_2: Label: GND; Manufacturer: Keystone; Manufacturer P/N: 1593-2; Vendor: Digikey; Vendor P/N: 1593-2K-ND
J10 J11 = BNC5-SCH_0: CONN,BNC,5 PINS; Part Number: CONNEX 112404
JP1 JP2 = JP3X1_079_NO_12_2
Q5 Q6 = MOS_FET_5: XSTR, N-CHANNEL DMOS FET
R87-R95 R98 R102 = RES0603_9: Manufacturer: ROHM; Manufacturer P/N: MCR03EZPFX4991; Vendor: Digikey; Vendor P/N: RHM4.99KHCT-ND; Volts/Amps/Watts: 0.1w
R96 = RES0603_5: Label: 1W; Manufacturer: VISHAY; Manufacturer P/N: CRCW251230R0JNEG; Tolerance: 5%; Vendor: Digikey; Vendor P/N: 541-30XCT-ND; Volts/Amps/Watts: 0.1W
R97 = RES0603_6: Label: 1W; Tolerance: 5%; Vendor: Digikey; Vendor P/N: 541-30XCT-ND; Volts/Amps/Watts: 0.1W
R99 R100 = RES0603_5: Label: 1W; Manufacturer: VISHAY; Manufacturer P/N: CRCW251230R0JNEG; Part Type: 2512; Tolerance: 5%; Vendor: Digikey; Vendor P/N: 541-30XCT-ND; Volts/Amps/Watts: 0.1W
R101 = POT_A_0
R103 = RES0603_11
U7 = LT1129CS8-3_0.3
U8 = LT1129CS8-3_3.3
U9 = LT1129CS8-3.3

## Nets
3V3: J7.5(LGKPWR) Q2.2(S) Q19.3(D) R84.1 R85.1 R113.1
+5V: C28.1 C30.2 R48.2 R88.2 R105.2 R106.2 U7.5(V+) U9.1(OUTPUT) U9.2(SENSE/ADJ)
GND_POWER: C25.2 C29.1 C30.1 C31.2 C32.2 C33.2 C34.2 CIN1.2 CIN2.2 CIN3.2 CIN4.2 CIN5.2 CIN6.2 CIN7.2 CIN8.2 CIN9.2 CIN10.2 CIN11.2 CIN12.2 CIN13.2 CIN14.2 CIN15.2 CIN16.2 CIN17.2 CIN18.2 CIN19.2 COUT1.2 COUT2.2 COUT3.2 COUT4.2 COUT5.2 COUT6.2 COUT7.2 COUT8.2 COUT9.2 COUT10.2 COUT11.2 COUT12.2 COUT13.2 COUT14.2 COUT15.2 COUT16.2 COUT17.2 COUT18.2 COUT19.2 COUT20.2 COUT21.2 COUT22.2 COUT23.2 COUT24.2 COUT25.2 COUT26.2 COUT27.2 COUT28.2 COUT29.2 COUT30.2 COUT31.2 COUT32.2 COUT33.2 COUT34.2 COUT35.2 COUT36.2 COUT37.2 COUT38.2 COUT39.2 COUT40.2 COUT41.2 COUT42.2 COUT43.2 COUT44.2 COUT45.2 COUT46.2 COUT47.2 COUT48.2 COUT49.2 COUT50.2 E4.1(TP) E24.1(TP) J2.1(TP) J3.1(TP) J6.1(TP) J7.3(GND) J7.10(GND) J10.2 J10.3 J10.4 J10.5 J11.2 J11.3 J11.4 J11.5 J12.11(GND) J12.12(GND) J13.11(GND) J13.12(GND) J14.2(GND) JP2.1 R3.2 R6.2 R18.2 R31.2 R32.1 R94.2 R96.1 R97.1 R99.1 R100.1 R112.2 U1.A4(GND) U1.A6(GND) U1.A7(GND) U1.A8(GND) U1.A9(GND) U1.A10(GND) U1.B4(GND) U1.B5(GND) U1.B6(GND) U1.B7(GND) U1.B8(GND) U1.B9(GND) U1.C4(GND) U1.C6(GND) U1.C7(GND) U1.C8(GND) U1.C9(GND) U1.D4(GND) U1.D7(GND) U1.E3(GND) U1.F3(GND) U1.F10(GND) U1.G3(GND) U1.G10(GND) U1.G11(GND) U1.G12(GND) U1.H3(GND) U1.H10(GND) U1.J4(GND) U1.J10(GND) U1.K4(GND) U1.K7(GND) U1.K8(GND) U1.K9(GND) U1.L4(GND) U1.L5(GND) U1.L6(GND) U1.L7(GND) U1.L8(GND) U1.L9(GND) U1.M4(GND) U1.M6(GND) U1.M7(GND) U1.M8(GND) U1.M9(GND) U1.M10(GND) U2.A6(GND) U2.A7(GND) U2.B6(GND) U2.B7(GND) U2.D1(GND) U2.D2(GND) U2.D3(GND) U2.D4(GND) U2.D9(GND) U2.D10(GND) U2.D11(GND) U2.D12(GND) U2.E1(GND) U2.E2(GND) U2.E3(GND) U2.E4(GND) U2.E10(GND) U2.E11(GND) U2.E12(GND) U2.F1(GND) U2.F2(GND) U2.F3(GND) U2.F10(GND) U2.F11(GND) U2.F12(GND) U2.G1(GND) U2.G3(GND) U2.G10(GND) U2.G12(GND) U2.H1(GND) U2.H2(GND) U2.H3(GND) U2.H4(GND) U2.H5(GND) U2.H6(GND) U2.H7(GND) U2.H9(GND) U2.H10(GND) U2.H11(GND) U2.H12(GND) U2.J1(GND) U2.J5(GND) U2.J8(GND) U2.J12(GND) U2.K1(GND) U2.K5(GND) U2.K6(GND) U2.K7(GND) U2.K8(GND) U2.K12(GND) U2.L1(GND) U2.L12(GND) U2.M1(GND) U2.M12(GND) U3.A6(GND) U3.A7(GND) U3.B6(GND) U3.B7(GND) U3.D1(GND) U3.D2(GND) U3.D3(GND) U3.D4(GND) U3.D9(GND) U3.D10(GND) U3.D11(GND) U3.D12(GND) U3.E1(GND) U3.E2(GND) U3.E3(GND) U3.E4(GND) U3.E10(GND) U3.E11(GND) U3.E12(GND) U3.F1(GND) U3.F2(GND) U3.F3(GND) U3.F10(GND) U3.F11(GND) U3.F12(GND) U3.G1(GND) U3.G3(GND) U3.G10(GND) U3.G12(GND) U3.H1(GND) U3.H2(GND) U3.H3(GND) U3.H4(GND) U3.H5(GND) U3.H6(GND) U3.H7(GND) U3.H9(GND) U3.H10(GND) U3.H11(GND) U3.H12(GND) U3.J1(GND) U3.J5(GND) U3.J8(GND) U3.J12(GND) U3.K1(GND) U3.K5(GND) U3.K6(GND) U3.K7(GND) U3.K8(GND) U3.K12(GND) U3.L1(GND) U3.L12(GND) U3.M1(GND) U3.M12(GND) U4.A6(GND) U4.A7(GND) U4.B6(GND) U4.B7(GND) U4.D1(GND) U4.D2(GND) U4.D3(GND) U4.D4(GND) U4.D9(GND) U4.D10(GND) U4.D11(GND) U4.D12(GND) U4.E1(GND) U4.E2(GND) U4.E3(GND) U4.E4(GND) U4.E10(GND) U4.E11(GND) U4.E12(GND) U4.F1(GND) U4.F2(GND) U4.F3(GND) U4.F10(GND) U4.F11(GND) U4.F12(GND) U4.G1(GND) U4.G3(GND) U4.G10(GND) U4.G12(GND) U4.H1(GND) U4.H2(GND) U4.H3(GND) U4.H4(GND) U4.H5(GND) U4.H6(GND) U4.H7(GND) U4.H9(GND) U4.H10(GND) U4.H11(GND) U4.H12(GND) U4.J1(GND) U4.J5(GND) U4.J8(GND) U4.J12(GND) U4.K1(GND) U4.K5(GND) U4.K6(GND) U4.K7(GND) U4.K8(GND) U4.K12(GND) U4.L1(GND) U4.L12(GND) U4.M1(GND) U4.M12(GND) U6.1(A0) U6.2(A1) U6.3(A2) U6.4(VSS) U6.7(WP) U9.3(GND) U9.6(GND) U9.7(GND)
GND_SIGNAL: C2.2 C3.2 C4.2 C7.2 C8.2 C9.2 C10.2 C11.2 C12.2 C13.2 C16.2 C17.2 C18.2 C19.2 C20.2 C21.2 C22.2 C23.2 C26.2 C28.2 E5.1(TP) E17.1(TP) E22.1(TP) Q1.2(S) Q3.2(S) Q4.2(S) R1.2 R6.1 R19.2 R21.1 R24.1 R25.1 R27.1 R28.1 R29.1 R30.1 R32.2 R36.2 R37.2 R40.1 R41.2 R58.2 R59.2 R63.1 R64.2 R68.1 R69.2 R86.2 R92.2 R93.2 R101.1 R101.2 R102.2 R118.2 SW1.3 SW2.3 U1.F7(SGND) U1.F8(SGND) U1.G7(SGND) U1.G8(SGND) U2.C7(SGND) U2.D6(SGND) U2.E8(DIFFP) U2.F6(SGND) U2.F7(SGND) U2.G6(SGND) U2.G7(SGND) U3.C7(SGND) U3.D6(SGND) U3.E8(DIFFP) U3.F6(SGND) U3.F7(SGND) U3.G6(SGND) U3.G7(SGND) U4.C7(SGND) U4.D6(SGND) U4.E8(DIFFP) U4.F6(SGND) U4.F7(SGND) U4.G6(SGND) U4.G7(SGND) U5.4(V-) U7.2(GND) U8.2(V-)
VDD25: E8.1(TP) U1.J6(VDD25)
VDD33: D8.1(CATHODE) E6.1(TP) Q19.2(S) R9.1 R10.1 R11.1 R12.1 R13.1 R14.1 R15.1 R16.1 R17.1 U1.J7(VDD33)
VIN: C31.1 CIN1.1 CIN2.1 CIN3.1 CIN4.1 CIN5.1 CIN6.1 CIN7.1 CIN8.1 CIN9.1 CIN10.1 CIN11.1 CIN12.1 CIN13.1 CIN14.1 CIN15.1 CIN16.1 CIN17.1 CIN18.1 CIN19.1 E3.1(TP) J4.1(TP) R7.1 R8.1 R33.1 R60.1 R65.1 R77.1 R82.1 R103.1 R104.2 R107.2 R108.2 R117.2 U1.A11(VIN0) U1.A12(VIN0) U1.B11(VIN0) U1.B12(VIN0) U1.C11(VIN0) U1.C12(VIN0) U1.D11(VIN0) U1.D12(VIN0) U1.E12(VIN0) U1.H12(VIN1) U1.J11(VIN1) U1.J12(VIN1) U1.K11(VIN1) U1.K12(VIN1) U1.L11(VIN1) U1.L12(VIN1) U1.M11(VIN1) U1.M12(VIN1) U2.J2(VIN) U2.J3(VIN) U2.J4(VIN) U2.J9(VIN) U2.J10(VIN) U2.J11(VIN) U2.K2(VIN) U2.K3(VIN) U2.K4(VIN) U2.K9(VIN) U2.K10(VIN) U2.K11(VIN) U2.L2(VIN) U2.L3(VIN) U2.L4(VIN) U2.L5(VIN) U2.L6(VIN) U2.L7(VIN) U2.L8(VIN) U2.L9(VIN) U2.L10(VIN) U2.L11(VIN) U2.M2(VIN) U2.M3(VIN) U2.M4(VIN) U2.M5(VIN) U2.M6(VIN) U2.M7(VIN) U2.M8(VIN) U2.M9(VIN) U2.M10(VIN) U2.M11(VIN) U3.J2(VIN) U3.J3(VIN) U3.J4(VIN) U3.J9(VIN) U3.J10(VIN) U3.J11(VIN) U3.K2(VIN) U3.K3(VIN) U3.K4(VIN) U3.K9(VIN) U3.K10(VIN) U3.K11(VIN) U3.L2(VIN) U3.L3(VIN) U3.L4(VIN) U3.L5(VIN) U3.L6(VIN) U3.L7(VIN) U3.L8(VIN) U3.L9(VIN) U3.L10(VIN) U3.L11(VIN) U3.M2(VIN) U3.M3(VIN) U3.M4(VIN) U3.M5(VIN) U3.M6(VIN) U3.M7(VIN) U3.M8(VIN) U3.M9(VIN) U3.M10(VIN) U3.M11(VIN) U4.J2(VIN) U4.J3(VIN) U4.J4(VIN) U4.J9(VIN) U4.J10(VIN) U4.J11(VIN) U4.K2(VIN) U4.K3(VIN) U4.K4(VIN) U4.K9(VIN) U4.K10(VIN) U4.K11(VIN) U4.L2(VIN) U4.L3(VIN) U4.L4(VIN) U4.L5(VIN) U4.L6(VIN) U4.L7(VIN) U4.L8(VIN) U4.L9(VIN) U4.L10(VIN) U4.L11(VIN) U4.M2(VIN) U4.M3(VIN) U4.M4(VIN) U4.M5(VIN) U4.M6(VIN) U4.M7(VIN) U4.M8(VIN) U4.M9(VIN) U4.M10(VIN) U4.M11(VIN) U9.8(VIN)
ALERTB: E12.1(TP) J7.6(ALERTB) J12.3(ALERTB) J13.3(ALERTB) Q2.1(G) R11.2 U1.E5(~{ALERT})
ASEL: R24.2 U1.G4(ASEL)
AUX3V4: D8.2(ANODE) J14.4(AUX3V4)
AUXVCC: C32.1 E25.1(A) J7.1(AUXP) J12.8(AUXP) J13.8(AUXP) R76.1 R115.1 U6.8(VCC)
CLKOUT_U1: Q1.3(D) R34.2 R45.1 R105.1
CLKOUT_U2: R61.2 U2.G5(CLKOUT)
CLKOUT_U3: R66.2 U3.G5(CLKOUT)
CLKOUT_U4: E10.1(TP) U4.G5(CLKOUT)
COMP: C10.1 C17.1 C21.1 U2.E6(COMP1) U2.E7(COMP2) U3.E6(COMP1) U3.E7(COMP2) U4.E6(COMP1) U4.E7(COMP2) U5.6(6_-IN_B) U5.7(7_OUT_B)
COMP0: C4.1 C5.1 R20.1 R50.1 R55.1 R109.2 U1.E8(COMP0a)
COMP1: C1.1 C2.1 R5.2 R50.2 U1.H8(COMP1a)
EESCL: J7.11(AUXSCL) R76.2 U6.6(SCL)
EESDA: J7.12(AUXSDA) R115.2 U6.5(SDA)
EXTVCC: C12.1 C19.1 C23.1 R106.1 U2.J7(EXTVCC) U3.J7(EXTVCC) U4.J7(EXTVCC)
FREQ_CFG: R25.2 U1.H4(FSWPHCFG)
GPIO0B: D5.2(ANODE) E18.1(TP) Q3.1(G) R14.2 R42.2 R54.2 R58.1 R71.2 R80.2 R109.1 U1.E4(~{GPIO0}) U5.5(5_+IN_B)
GPIO1B: D4.2(ANODE) E11.1(TP) Q4.1(G) R15.2 R42.1 R78.2 R81.2 U1.F4(~{GPIO1})
INTVCC: E2.1(TP) R7.2 R46.2 U1.F9(INTVCC) U1.G9(INTVCC)
INTVCC_U2: C11.1 R35.1 R39.1 R45.2 R104.1 U2.E9(DIFFN) U2.H8(INTVCC)
INTVCC_U3: C18.1 R62.1 R107.1 U3.E9(DIFFN) U3.H8(INTVCC)
INTVCC_U4: C22.1 R67.1 R108.1 U4.E9(DIFFN) U4.H8(INTVCC)
RUN: R38.1 R117.1 R118.1 U2.F5(RUN1) U2.F9(RUN2) U3.F5(RUN1) U3.F9(RUN2) U4.F5(RUN1) U4.F9(RUN2)
RUN0: D5.1(CATHODE) E19.1(TP) R16.2 R22.2 R38.2 R44.2 R70.2 R78.1 R111.2 R114.2 SW1.1 SW1.2 U1.F5(RUN0)
RUN1: D4.1(CATHODE) E21.1(TP) R17.2 R26.2 R44.1 R71.1 R72.2 R73.2 R110.2 SW2.1 SW2.2 U1.F6(RUN1)
SCL: E14.1(TP) J7.4(SCL) J12.6(SCL) J13.6(SCL) J14.3(SCL) R12.2 U1.E6(SCL)
SDA: E13.1(TP) J7.2(SDA) J12.4(SDA) J13.4(SDA) J14.1(SDA) R13.2 U1.D6(SDA)
SHARE_CLK: E15.1(TP) R10.2 R75.1 U1.H7(SHARE_CLK)
SYNC: E16.1(TP) Q1.1(G) R9.2 R83.1 U1.E7(SYNC)
TRACK: R37.1 U2.D8(TRACK2) U2.E5(TRACK1) U3.D8(TRACK2) U3.E5(TRACK1) U4.D8(TRACK2) U4.E5(TRACK1)
VFB: C9.1 C16.1 C20.1 R35.2 R36.1 U2.D5(VFB1) U2.D7(VFB2) U3.D5(VFB1) U3.D7(VFB2) U4.D5(VFB1) U4.D7(VFB2)
VOSNS0-: C6.2 E9.1(TP) R31.1 U1.E9(VOSNS0-)
VOUT0: C25.1 COUT8.1 COUT9.1 COUT10.1 COUT11.1 COUT12.1 COUT13.1 COUT14.1 COUT15.1 COUT16.1 COUT17.1 COUT18.1 COUT19.1 COUT20.1 COUT21.1 COUT22.1 COUT23.1 COUT24.1 COUT25.1 COUT26.1 COUT27.1 COUT28.1 COUT29.1 COUT30.1 COUT31.1 COUT32.1 COUT33.1 COUT34.1 COUT35.1 COUT36.1 COUT37.1 COUT38.1 COUT39.1 COUT40.1 COUT41.1 COUT42.1 COUT43.1 COUT44.1 COUT45.1 COUT46.1 COUT47.1 COUT48.1 COUT49.1 J5.1(TP) J10.1 P7.1(TP) P8.1(TP) P10.1(TP) P12.1(TP) P14.1(TP) P16.1(TP) P18.1(TP) Q5.5(D) Q6.5(D) R23.2 R43.2 R49.2 R52.2 R56.2 R96.2 U1.A1(VOUT0) U1.A2(VOUT0) U1.A3(VOUT0) U1.B1(VOUT0) U1.B2(VOUT0) U1.B3(VOUT0) U1.C1(VOUT0) U1.C2(VOUT0) U1.C3(VOUT0) U1.D1(VOUT0) U1.D2(VOUT0) U1.D3(VOUT0) U2.A1(VOUT1) U2.A2(VOUT1) U2.A3(VOUT1) U2.A4(VOUT1) U2.A5(VOUT1) U2.A8(VOUT2) U2.A9(VOUT2) U2.A10(VOUT2) U2.A11(VOUT2) U2.A12(VOUT2) U2.B1(VOUT1) U2.B2(VOUT1) U2.B3(VOUT1) U2.B4(VOUT1) U2.B5(VOUT1) U2.B8(VOUT2) U2.B9(VOUT2) U2.B10(VOUT2) U2.B11(VOUT2) U2.B12(VOUT2) U2.C1(VOUT1) U2.C2(VOUT1) U2.C3(VOUT1) U2.C4(VOUT1) U2.C9(VOUT2) U2.C10(VOUT2) U2.C11(VOUT2) U2.C12(VOUT2) U3.A1(VOUT1) U3.A2(VOUT1) U3.A3(VOUT1) U3.A4(VOUT1) U3.A5(VOUT1) U3.A8(VOUT2) U3.A9(VOUT2) U3.A10(VOUT2) U3.A11(VOUT2) U3.A12(VOUT2) U3.B1(VOUT1) U3.B2(VOUT1) U3.B3(VOUT1) U3.B4(VOUT1) U3.B5(VOUT1) U3.B8(VOUT2) U3.B9(VOUT2) U3.B10(VOUT2) U3.B11(VOUT2) U3.B12(VOUT2) U3.C1(VOUT1) U3.C2(VOUT1) U3.C3(VOUT1) U3.C4(VOUT1) U3.C9(VOUT2) U3.C10(VOUT2) U3.C11(VOUT2) U3.C12(VOUT2) U4.A1(VOUT1) U4.A2(VOUT1) U4.A3(VOUT1) U4.A4(VOUT1) U4.A5(VOUT1) U4.A8(VOUT2) U4.A9(VOUT2) U4.A10(VOUT2) U4.A11(VOUT2) U4.A12(VOUT2) U4.B1(VOUT1) U4.B2(VOUT1) U4.B3(VOUT1) U4.B4(VOUT1) U4.B5(VOUT1) U4.B8(VOUT2) U4.B9(VOUT2) U4.B10(VOUT2) U4.B11(VOUT2) U4.B12(VOUT2) U4.C1(VOUT1) U4.C2(VOUT1) U4.C3(VOUT1) U4.C4(VOUT1) U4.C9(VOUT2) U4.C10(VOUT2) U4.C11(VOUT2) U4.C12(VOUT2)
VOUT0_CFG: R27.2 U1.G5(VOUT0CFG)
VOUT0_SNS: C6.1 E7.1(TP) R23.1 R116.1 U1.D9(VOSNS0+)
VOUT1: COUT1.1 COUT2.1 COUT3.1 COUT4.1 COUT5.1 COUT6.1 COUT7.1 COUT50.1 J1.1(TP) P3.1(TP) R2.1 R43.1 R49.1 R52.1 R56.1 R97.2 U1.J1(VOUT1) U1.J2(VOUT1) U1.J3(VOUT1) U1.K1(VOUT1) U1.K2(VOUT1) U1.K3(VOUT1) U1.L1(VOUT1) U1.L2(VOUT1) U1.L3(VOUT1) U1.M1(VOUT1) U1.M2(VOUT1) U1.M3(VOUT1)
VOUT1_CFG: R29.2 U1.G6(VOUT1CFG)
VOUT1_SNS: C3.1 E1.1(TP) R2.2 R116.2 U1.H9(VOSNS1)
VTRIM0_CFG: R28.2 U1.H5(VTRIM0CFG)
VTRIM1_CFG: R30.2 U1.H6(VTRIM1CFG)
N16992964: R8.2 U1.F11(SVIN) U1.F12(SVIN)
N17002004: C5.2 R19.1
N17134921: P5.1(TP) U1.D10(VORB0+)
N17135374: P6.1(TP) U1.E10(VORB0-)
N17138086: R20.2 U1.D8(COMP0b)
N17139451: U1.C5(TSNS0b) U1.D5(TSNS0a)
N17139909: U1.F1(ISNS0b+) U1.F2(ISNS0a+)
N17140369: U1.E1(ISNS0b-) U1.E2(ISNS0a-)
N17141676: R18.1 U1.A5(SNUB0)
N17154876: R5.1 U1.J8(COMP1b)
N17160063: P2.1(TP) U1.J9(VORB1)
N17162925: R4.1 U1.J5(TSNS1a)
N17163420: R4.2 U1.K5(TSNS1b)
N17164914: U1.H1(ISNS1b+) U1.H2(ISNS1a+)
N17165415: U1.G1(ISNS1b-) U1.G2(ISNS1a-)
N17166430: P1.1(TP) U1.L10(SW1)
N17168866: R3.1 U1.M5(SNUB1)
N17491667: R21.2 U1.K6(WP)
N17988510: C1.2 R1.1
N18073508: P4.1(TP) U1.B10(SW0)
N18200028: C7.1 R22.1
N18208059: C8.1 R26.1
N18216707: R39.2 R41.1 U2.G4(PHASMD)
N18217155: R33.2 U2.J6(TEMP)
N18217367: P9.1(TP) U2.G2(SW1)
N18217715: R40.2 U2.C6(FSET)
N18217746: P11.1(TP) U2.G11(SW2)
N18217780: R34.1 U2.F4(MODE-PLLIN)
N18263831: R55.2 U5.3(+IN_A)
N18263852: C13.1 R46.1 R48.1 U5.8(8V+)
N18263864: R47.2 R59.1 U5.2(-IN_A)
N18263872: R47.1 R51.2 U5.1(OUTA)
N18263897: R51.1 R54.1
N18369636: R62.2 R64.1 U3.G4(PHASMD)
N18369996: R60.2 U3.J6(TEMP)
N18370176: P13.1(TP) U3.G2(SW1)
N18370404: R63.2 U3.C6(FSET)
N18370423: P15.1(TP) U3.G11(SW2)
N18370435: R61.1 U3.F4(MODE-PLLIN)
N18388578: R67.2 R69.1 U4.G4(PHASMD)
N18388790: R65.2 U4.J6(TEMP)
N18389120: P17.1(TP) U4.G2(SW1)
N18389347: R68.2 U4.C6(FSET)
N18389368: P19.1(TP) U4.G11(SW2)
N18389380: R66.1 U4.F4(MODE-PLLIN)
N18409032: JP1.1 R91.2
N18409036: JP1.2 JP1.3 Q5.4(G) Q6.4(G) R87.2 R94.1
N18409046: E23.1(TP) R87.1
N18409068: C29.2 J11.1 Q5.1(S) Q5.2(S) Q5.3(S) Q6.1(S) Q6.2(S) Q6.3(S) R95.2 R99.2 R100.2
N18409078: JP2.2 R103.2 U9.5(~{SHDN})
N18409311: R88.1 R93.1 U7.4(DIV)
N18409327: C26.1 R89.1 U7.6(OUT) U8.5(V+)
N18409569: R98.2 R101.3 R102.1
N18409595: C27.1 R91.1 U8.1(VOUT)
N18409609: R89.2 R98.1 U8.3(+IN)
N18409611: C27.2 R95.1 U8.4(-IN)
N18409691: R90.2 U7.3(SET)
N18409693: R90.1 R92.1 U7.1(MOD)
N18860071: D2.1(A) R84.2
N18860073: D2.2(K) Q3.3(D)
N18860079: D1.2(K) Q4.3(D)
N18860089: D3.1(A) Q2.3(D)
N18860104: D3.2(K) R86.1
N18860365: J12.1(FAULTB) J13.1(FAULTB) R80.1 R81.1 R110.1 R111.1
N18860379: J7.8(OUTEN_0) R74.1
N18860381: J7.9(OUTEN_1) R79.1
N18860393: J12.2(CTRL) J13.2(CTRL) R72.1 R74.2 R79.2 R114.1
N18860443: C33.1 R73.1
N18860445: C34.1 R70.1
N18860467: Q19.1(G) R77.2 R112.1
N18860497: J12.5(SHARE_CLK) J13.5(SHARE_CLK) R75.2
N18860499: J12.7(RESETB) J13.7(RESETB)
N18860501: J12.9(UNUSED) J13.9(UNUSED) R83.2
N18860513: J12.13(12V) J12.14(12V) J13.13(12V) J13.14(12V) R82.2
N18860585: J12.10(UNUSED) J13.10(UNUSED) R113.2
N18871413: D1.1(A) R85.2

Not connected (* = marked no-connect by the designer): J7 7(GPIO_1); JP2 3; SW1 4 5 6; SW2 4 5 6; U1 C10(DNC) E11(DNC) H11(DNC) K10(DNC); U2 C5(VOUTS1) C8(VOUTS2) F8(DIFFOUT) G8(PGOOD2) G9(PGOOD1); U3 C5(VOUTS1) C8(VOUTS2) F8(DIFFOUT) G8(PGOOD2) G9(PGOOD1); U4 C5(VOUTS1) C8(VOUTS2) F8(DIFFOUT) G8(PGOOD2) G9(PGOOD1); U9 4(NC)*

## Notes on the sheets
sheet 1
- 1210
- OPT
- 1210
- 1210
- 1210
- 1210
- 0.035 VIA
- 0805
- TESTPOINTS
- *
- 4.5V - 15V
- 1210
- 35V
- 1210
- 1210
- 1210
- 1210
- 0805
- RUN0
- ON
- OFF
- RUN1
- ON
- 1V/186A
- 1210
- 1210
- 1210
- 1210
- OFF
- NOTE: UNLESS OTHERWISE SPECIFIED
- 1.  ALL RESISTORS ARE 0603.
       ALL CAPACITORS ARE 0603.
- *
- WHEN VIN < 5.75V, SHORT INTVCC TO VIN WITH R7=0 0hm.
- µMODULE REGULATOR  WITH POWER SYSTEM MANAGEMENT
sheet 2
- 1210
- 1210
- 1210
- 1210
- 1210
- 1210
- 1210
- OPTIONAL OUTPUT SP-CAP
- 1210
- 1210
- 1210
- OPTIONAL JUMPER FOR  SINGLE
  OUTPUT CONFIGURATION
- µMODULE REGULATOR  WITH POWER SYSTEM MANAGEMENT
sheet 3
- 1210
- 1210
- 1210
- 1210
- 1210
- 1210
- 1210
- 1210
- 1210
- 1210
- µMODULE REGULATOR  WITH POWER SYSTEM MANAGEMENT
sheet 4
- 1210
- 1210
- 1210
- 1210
- 1210
- 1210
- 1210
- 1210
- 1210
- 1210
- µMODULE REGULATOR  WITH POWER SYSTEM MANAGEMENT
sheet 5
- ALL PARTS ON THIS PAGE ARE FOR DEMO ONLY, NOT NEEDED IN CUSTOMER DESIGN
- TO DC2086A
- TO DC1613A
- 1206
- OPTIONAL CIRCUIT FOR PROGRAMMING
  WITHOUT VIN
- PSM STACKING CONNECTORS:
- J1, MALE, CONN  HEADER 14POS 2MM R/A GOLD, Molex Connector Corp. 87760-1416
- J2, FEMALE, CONN RECEPT 2MM DUAL R/A 14POS, Sullins Conn. NPPN072FJFN-RC
- GPIO0
- GPIO1
- ALERTB
- µMODULE REGULATOR  WITH POWER SYSTEM MANAGEMENT
sheet 6
- ALL PARTS ON THIS PAGE ARE FOR DEMO ONLY, NOT NEEDED IN CUSTOMER DESIGN
- DYNAMIC LOAD CIRCUIT
- 70Hz, 3% Duty Cycle
- VOUT0
- PULSE
- INT
- EXT
- IOUT
  TST
- 0805
- 2010
- 2010
- 1%
- OPT
- OPT
- BLEEDER LOADS
- 1%
- BIAS
- ON
- OFF
- µMODULE REGULATOR  WITH POWER SYSTEM MANAGEMENT
- µModule REGULATOR WITH DIGITAL POWER MAN
